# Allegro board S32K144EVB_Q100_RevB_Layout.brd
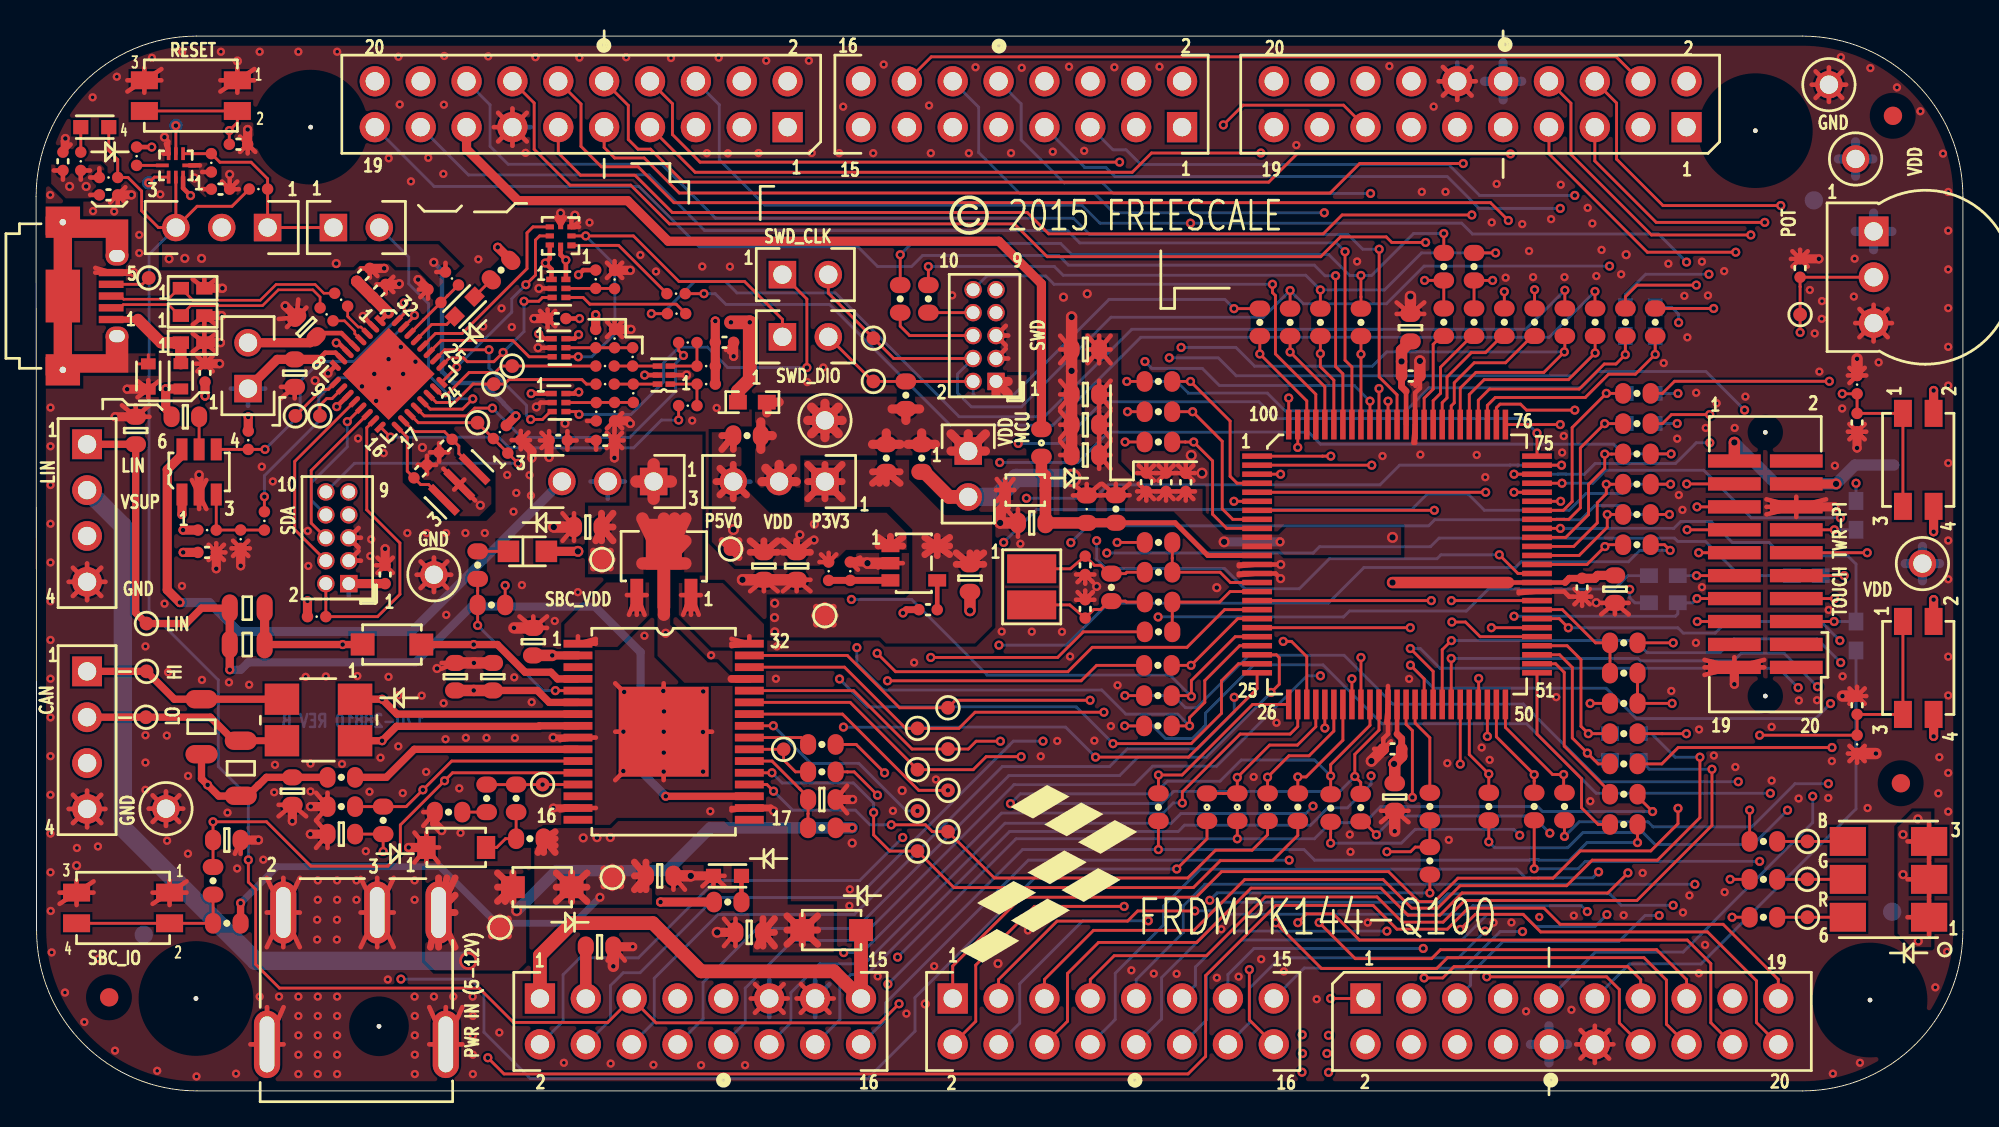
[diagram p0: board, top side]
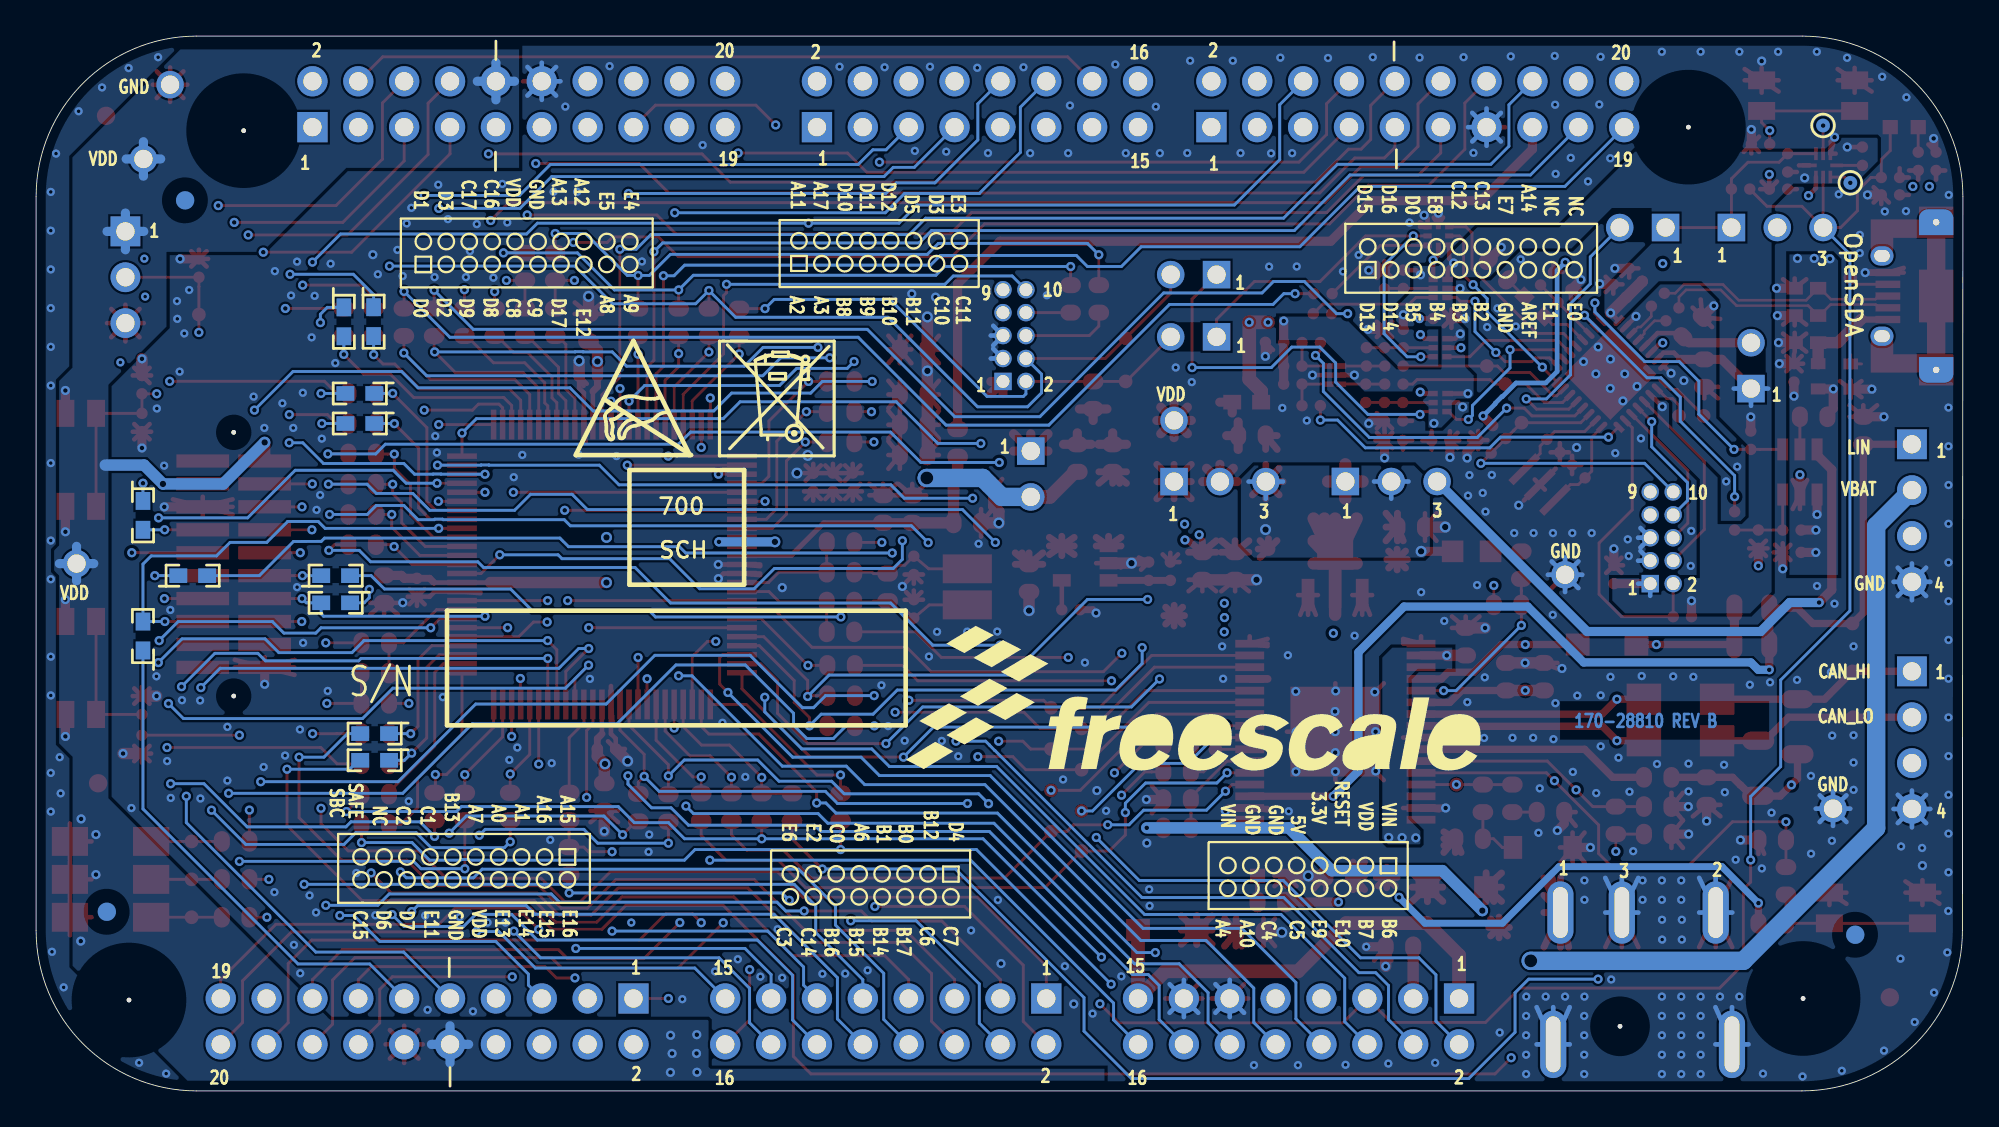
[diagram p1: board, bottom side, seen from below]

Outline 106.71 x 58.42 mm; copper layers: TOP, L2_GND, L3_MIX, BOTTOM. Coordinates in mm from the lower left corner of the outline.
Outline path: 0,49.53 arc(2.6,55.82) 8.89,58.42 97.82,58.42 arc(104.1,55.82) 106.71,49.53 106.71,8.89 arc(104.1,2.6) 97.82,0 8.92,0 arc(2.63,2.6) 0.03,8.89 0.03,8.89 0,49.53

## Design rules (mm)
net group CLOCK: nets SDA_EXTAL SDA_XTAL
net group SDA_USB_CONN_D: nets SDA_USB_CONN_DN SDA_USB_CONN_DP
net group USB_SI_CONN_D: nets SDA_USB_DN SDA_USB_DP
net group POW: nets MIC2005_CSLEW P5V_SDA POWER_EN SDA_RST SDA_USB_P5V_SENSE VREFH VTRG_EN
net group POWER_SPACE: nets P5V0_SDA_USB_CONN_VBUS P5V_SDA_PSW PWR_LED SDA_VOUT33 VCAN VIN
nets with their own width: min track width 0.254; nets GND

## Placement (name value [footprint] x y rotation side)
C1  1000pF  [CC0402_25]  11.21 52.43 0 top
C2  4.7uF  [CC0402_25]  1.49 51.49 90 top
C3  4.7uF  [CC0402_25]  10.21 49.94 0 top
C4  0.1UF  [CC0402_25]  4.01 49.63 0 top
C5  0.1UF  [CC0402_25]  97.69 45.57 90 top
C6  1.0UF  [CC0402_25]  18.12 45.2 45 top
C7  0.1UF  [CC0402_25]  19 44.31 45 top
C8  4.7uF  [CC0402_25]  28.83 42.77 180 top
C9  2.2UF  [CC0603_OV]  14.97 42.31 135 top
C10  0.1UF  [CC0402_25]  38.12 41.46 0 top
C11  10uF  [CC0402_25]  9.35 39.77 90 top
C12  10uF  [CC0603_OV]  14.32 39.75 270 top
C15  18PF  [CC0603_OV]  8.26 37.34 0 top
C16  0.1UF  [CC0402_25]  100.84 37.02 270 top
C17  220PF  [CC0603_OV]  5.51 36.58 90 top
C18  4.7uF  [CC0402_25]  28.92 36.03 180 top
C19  0.1UF  [CC0402_25]  31.52 36.03 0 top
C20  22PF  [CC0402_25]  22.68 35.73 225 top
C21  10uF  [CC0603_OV]  40.3 29.07 270 top
C22  0.1uF  [CC0603_OV]  42.12 29.07 270 top
C23  22PF  [CC0402_25]  21.29 34.31 45 top
C24  10uF  [CC0603_OV]  51.72 28.4 270 top
C25  0.1UF  [CC0402_25]  9.47 29.82 0 top
C26  0.1UF  [CC0402_25]  19.33 28.6 90 top
C27  10uF  [CC0603_OV]  30.55 31.23 180 top
C28  0.1UF  [CC0402_25]  100.85 21.36 90 top
C29  220PF  [CC0603_OV]  27.53 24.88 90 top
C30  2.2UF  [CC0603_OV]  23.22 22.94 90 top
C31  0.1uF  [CC0603_OV]  25.29 22.94 90 top
C40  4700 PF  [CC0603_OV]  14.19 16.6 270 top
C42  0.1uF  [CC0603_OV]  43.52 16.14 0 top
C43  1UF  [CC0603_OV]  58.11 38.57 180 top
C44  82pF  [CC0603_OV]  16.9 14.22 180 top
C46  0.1uF  [CC0603_OV]  10.56 13.89 0 top
C47  0.1uF  [CC0603_OV]  34.53 11.91 0 top
C49  2.2UF  [CC0603_OV]  31.2 7.98 0 top
C59  0.01UF  [CC0402_25]  49.4 26.65 180 top
C126  12PF  [CC0402_25]  58.1 29.11 270 top
C127  12PF  [CC0402_25]  58.1 26.69 90 top
C128  10uF  [CC0603_OV]  39.49 8.78 180 top
C129  1UF  [CC0603_OV]  58.11 35.22 180 top
C131  1UF  [CC0603_OV]  58.11 36.89 180 top
C133  1UF  [CC0603_OV]  76.11 42.27 90 top
C137  1UF  [CC0603_OV]  75.24 16.28 270 top
C140  0.1uF  [CC0402_25]  62.58 33.71 90 top
C141  0.1uF  [CC0402_25]  75.12 18.94 180 top
C142  0.1uF  [CC0402_25]  76.13 39.59 0 top
C143  0.1uF  [CC0402_25]  85.62 27.88 270 top
C144  0.1uF  [CC0402_25]  61.48 33.71 90 top
C145  0.1uF  [CC0402_25]  63.67 33.71 90 top
C146  1UF  [CC0603_OV]  87.43 27.79 270 top
C147  1000PF  [CC0603_OV]  58.11 41.06 180 top
C148  1000PF  [CC0603_OV]  55.14 31.46 180 top
D1  RED  [LED_0603]  3.25 53.38 0 top
D2  LED GREEN  [LED_0603]  23.73 43.44 225 top
D3  GREEN  [LED_0603]  38.29 11.91 180 top
D4  HSMS-C170  [HSMX-C170]  27.21 29.88 180 top
D6  MBR230LSFT1G  [SOD-123]  19.71 24.72 180 top
D7  3.0V  [SOD-323-A]  54.78 33.28 180 top
D8  MMSZ8V2T1G  [SOD123]  23.27 13.48 180 top
D9  MBR230LSFT1G  [SOD-123]  28.03 11.28 0 top
D11  LED RED/GRN/BL  [LED6_5X6MM]  102.58 11.72 180 top
D13  MBR230LSFT1G  [SOD-123]  44.06 8.91 180 top
J1  CON_2X8  [HDR208_ESQ_SKT]  63.46 53.38 270 top
J2  SKT_2x10  [HDR210_ESQ_SKT]  41.62 53.38 270 top
J3  CON_2X8  [HDR208_ESQ_SKT]  27.9 5.12 90 top
J4  CON_2X8  [HDR208_ESQ_SKT]  50.76 5.12 90 top
J5  SKT_2x10  [HDR210_ESQ_SKT]  73.62 5.12 90 top
J6  SKT_2x10  [HDR210_ESQ_SKT]  91.4 53.38 270 top
J7  USB_MICRO_AB  [CON_MICROAB_10F_25_SM_RA]  1.58 44.02 0 top
J8  HDR 1X2 TH  [SH_HDR102_BOTTOM]  41.33 45.21 90 top
J9  HDR 1X2 TH  [SH_HDR102_BOTTOM]  11.73 38.9 180 top
J10  HDR TH 1X3  [HDR103]  43.69 33.75 270 top
J11  HDR 1X4 RA  [CON_HDR_4M_100_TH_RA]  2.82 35.81 270 top
J12  HDR 2X5  [HDR_5X2_FTSH_TH_NSP]  17.32 28.09 180 top
J13  HDR 1X4 RA  [CON_HDR_4M_100_TH_RA]  2.82 23.24 270 top
J14  HDR 2X5  [HDR_5X2_FTSH_TH_NSP]  53.16 39.29 180 top
J15  HDR 1X2 TH  [HDR102]  51.62 35.44 0 top
J16  CON PWR 3  [CON3_PWR_JACK_TH_PJ051A]  22.29 9.88 90 top
J25  CON_2X10  [CON_TFM_20M_50_SM]  95.76 29.17 0 top
J104  HDR_1X3  [HDR103]  12.82 47.82 270 top
J105  HDR 1X2 TH  [SH_HDR102_BOTTOM]  16.46 47.82 90 top
J106  HDR 1X2 TH  [SH_HDR102_BOTTOM]  41.33 41.76 90 top
J107  HDR_1X3  [HDR103]  34.2 33.75 270 top
L1  330 OHM  [IND_1608]  8.02 39.58 270 top
L2  330 OHM  [IND_1608]  6.21 39.57 270 top
L4  B82789C0513N002  [IND_1812_4P]  15.64 20.54 270 top
NOREF  -  []  6.99 51.26 90 top
NOREF#2  -  []  51.49 7.8 0 top
NOREF#3  -  []  -35.57 -162.37 0 top
NOREF#4  -  []  10.97 53.32 90 top
NOREF#5  -  []  18.76 53.38 90 top
NOREF#6  -  [unnamed#2]  102.83 54.01 0 top
NOREF#7  -  []  97.82 0 90 top
NOREF#8  -  []  51.8 48.63 0 top
NOREF#9  -  []  51.17 7.1 0 top
NOREF#10  -  []  102.43 32.55 90 top
NOREF#11  -  []  2.42 11.93 0 top
NOREF#12  -  []  8.89 58.42 0 top
NOREF#13  -  []  103.38 26 0 top
NOREF#14  -  []  53.34 39.01 0 top
NOREF#15  -  []  154.88 58.67 0 top
NOREF#16  -  []  34.41 40.15 0 top
NOREF#17  -  []  98.13 1.31 0 top
NOREF#18  -  []  100.03 8.67 90 top
NOREF#19  -  []  18.76 53.38 0 top
NOREF#20  -  []  7.74 51.91 0 top
NOREF#21  -  []  100.33 9.62 90 top
NOREF#22  -  []  10.09 25.1 0 top
NOREF#23  -  [unnamed#2]  95.21 53.18 0 top
NOREF#24  -  []  68.54 53.38 0 top
NOREF#25  -  []  -67.9 -131.95 0 top
NOREF#26  -  []  -16.59 -34.16 0 top
NOREF#27  -  [unnamed#2]  4.05 5.18 0 top
NOREF#28  -  []  22.19 57.19 90 top
NOREF#29  -  []  17.11 57.19 0 top
NOREF#30  -  [unnamed#2]  15.2 53.38 0 top
NOREF#31  -  []  102.43 37.35 0 top
NOREF#32  -  []  102.43 21.03 90 top
NOREF#33  -  []  88.86 53.38 0 top
NOREF#34  -  []  73.62 5.12 0 top
NOREF#35  -  []  5.99 55.97 0 top
NOREF#36  -  []  95.76 36.47 270 top
NOREF#37  -  []  102.43 25.83 0 top
NOREF#38  -  []  106.71 8.89 90 top
NOREF#39  -  []  -408 -337.34 0 top
NOREF#40  -  [unnamed#2]  103.27 17.04 0 top
NOREF#41  -  []  68.54 53.38 90 top
NOREF#42  -  []  103.38 37.53 0 top
NOREF#43  -  []  39.08 53.38 0 top
NOREF#44  -  []  66.89 57.19 0 top
NOREF#45  -  []  71.97 57.19 90 top
NOREF#46  -  []  100.33 13.82 0 top
NOREF#47  -  [unnamed#2]  101.56 5.03 0 top
NOREF#48  -  []  -381.97 187.81 0 top
NOREF#49  -  []  7.01 51.88 0 top
NOREF#50  -  []  7.94 50.64 90 top
NOREF#51  -  []  8.88 5.05 0 top
NOREF#52  -  []  0 49.53 0 top
NOREF#53  -  []  103.21 1.31 90 top
NOREF#54  -  []  78.85 41.27 0 top
NOREF#55  -  []  6.17 56.92 0 top
NOREF#56  -  []  103.38 20.85 90 top
NOREF#57  -  []  96.48 2.58 90 top
NOREF#58  -  []  103.38 32.38 90 top
NOREF#59  -  [unnamed#2]  8.85 5.12 0 top
NOREF#60  -  []  100.03 14.77 0 top
NOREF#61  -  []  7.22 8.33 90 top
NOREF#62  -  []  2.24 10.98 0 top
NOREF#63  -  []  11.15 54.27 90 top
NOREF#64  -  []  7.39 9.28 90 top
NOREF#65  -  []  73.62 5.12 0 top
NOREF#66  -  []  91.82 42.06 180 bottom
NOREF#67  -  []  39.89 1.44 180 bottom
NOREF#68  -  []  54.61 8.05 180 bottom
NOREF#69  -  []  70.31 54.49 0 bottom
NOREF#70  -  [unnamed#2]  98.45 49.32 180 bottom
NOREF#71  -  []  54.66 15.42 180 bottom
NOREF#72  -  [unnamed#2]  102.79 9.92 180 bottom
NOREF#73  -  []  171.98 13.39 270 bottom
NOREF#74  -  [unnamed#2]  5.96 8.65 180 bottom
NOREF#75  -  []  65.81 40.19 180 bottom
NOREF#76  -  []  38.46 17.65 180 bottom
Q1  BCX53  [SOT89_31]  34.76 29.61 0 top
R1  4.7K  [RC0402_25]  5.57 51.77 90 top
R2  330 OHM  [RC0402_25]  2.47 51.49 270 top
R3  10.0K  [RC0402_25]  9.7 51.4 90 top
R4  180K  [RC0402_25]  4.01 50.59 0 top
R5  0  [RC0402_25]  12.31 49.95 180 top
R12  220  [RC0603_OV]  25.75 45.46 225 top
R13  5K  [POT3_3352T]  101.76 47.6 270 top
R14  4.7K  [RC0402_25]  23.03 45 315 top
R15  4.7K  [RC0402_25]  30.99 44.95 270 top
R16  10.0K  [RC0402_25]  32.03 44.94 90 top
R18  0  [RC0402_25]  35.44 44.16 0 top
R20  10.0K  [RC0402_25]  22.06 44.03 135 top
R21  33  [RC0402_25]  16.89 43.82 315 top
R24  0  [RC0402_25]  35.47 43.05 180 top
R25  33  [RC0402_25]  16.09 43.01 315 top
R30  4.7K  [RC0402_25]  30.99 41.67 270 top
R31  10.0K  [RC0402_25]  32.03 41.67 90 top
R32  0  [RC0402_25]  36.09 41.45 180 top
R35  0  [RC0402_25]  33.04 40.65 90 top
R38  0  [RC0402_25]  31.51 40.15 180 top
R39  10.0K  [RC0402_25]  37.11 40.15 0 top
R41  0  [RC0402_25]  31.51 39.15 180 top
R42  10.0K  [RC0402_25]  37.11 39.15 180 top
R44  10.0K  [RC0402_25]  100.85 39.12 90 top
R47  0  [RC0402_25]  33.07 38.64 270 top
R49  0  [RC0402_25]  36.09 37.95 180 top
R51  10.0K  [RC0402_25]  32.03 37.62 270 top
R52  4.7K  [RC0402_25]  31.02 37.61 90 top
R56  330  [RC0603_OV]  38.3 10.46 180 top
R57  4.7K  [RC0402_25]  25.68 36.49 225 top
R60  10.0K  [RC0402_25]  11.75 36.04 270 top
R62  10.0K  [RC0402_25]  26.48 35.68 45 top
R63  0  [RC0603_OV]  47.08 35.05 90 top
R64  0  [RC0603_OV]  39.37 36.29 0 top
R68  15K  [RC0402_25]  11.33 30.56 270 top
R69  1.0K  [RC0402_25]  12.64 31.57 270 top
R70  10.0K  [RC0402_25]  9.47 31.06 0 top
R73  1K  [RC0603_OV]  24.46 29.12 270 top
R74  10.0K  [RC0402_25]  100.85 19.19 270 top
R75  0  [RC0603_OV]  25.21 26.92 180 top
R77  10.0K  [RC0402_25]  15.54 26.27 0 top
R80  2K  [RC0805_OV]  11.69 24.72 0 top
R81  0  [RC0603_OV]  62.16 25.42 0 top
R84  0  [RC0603_OV]  62.16 27.08 180 top
R88  0  [RC0603_OV]  62.16 28.73 180 top
R90  0  [RC0603_OV]  62.16 30.38 0 top
R91  1.0M  [RC0603_OV]  59.55 27.89 270 top
R92  60.4  [RC1206_OV]  9.16 20.17 270 top
R93  0  [RC0603_OV]  43.52 19.19 180 top
R95  220  [RC0603_OV]  95.66 13.82 180 top
R96  220  [RC0603_OV]  95.66 11.72 180 top
R97  220  [RC0603_OV]  95.66 9.62 180 top
R98  60.4  [RC1206_OV]  11.34 17.87 270 top
R99  1K  [RC0603_OV]  59.8 32.23 270 top
R100  0  [RC0603_OV]  16.9 17.37 0 top
R102  0  [RC0603_OV]  43.52 17.67 180 top
R103  0  [RC0603_OV]  58.18 32.22 270 top
R104  0  [RC0603_OV]  24.95 16.2 90 top
R105  0  [RC0603_OV]  26.58 16.2 90 top
R107  4.7K  [RC0603_OV]  16.9 15.75 180 top
R108  4.7K  [RC0603_OV]  22.84 15.44 180 top
R109  0  [RC0603_OV]  55.67 35.89 90 top
R110  1K  [RC0603_OV]  43.52 14.57 180 top
R112  120.0  [RC0603_OV]  19.22 14.98 270 top
R113  4.7K  [RC0603_OV]  27.35 13.97 180 top
R116  12.0K  [RC0603_OV]  9.8 11.64 90 top
R117  0  [RC0603_OV]  49.04 35.05 270 top
R118  12.0K  [RC0603_OV]  10.56 9.28 180 top
R119  0  [RC0603_OV]  47.85 43.87 90 top
R120  0  [RC0603_OV]  49.41 43.87 90 top
R121  10K  [RC0603_OV]  48.17 38.53 90 top
R122  0  [RC0603_OV]  67.77 42.57 90 top
R123  0  [RC0603_OV]  73.37 42.56 90 top
R124  0  [RC0603_OV]  88.65 35.28 0 top
R125  0  [RC0603_OV]  88.65 33.6 0 top
R126  0  [RC0603_OV]  88.65 31.93 0 top
R127  0  [RC0603_OV]  69.45 42.56 90 top
R128  0  [RC0603_OV]  71.12 42.57 90 top
R129  0  [RC0603_OV]  88.65 30.25 180 top
R130  0  [RC0603_OV]  69.87 15.71 90 top
R131  0  [RC0603_OV]  68.2 15.71 90 top
R132  0  [RC0603_OV]  66.52 15.71 90 top
R133  0  [RC0603_OV]  87.92 16.43 180 top
R134  0  [RC0603_OV]  87.92 14.76 180 top
R135  0  [RC0603_OV]  62.15 15.71 90 top
R136  0  [RC0603_OV]  62.15 37.62 0 top
R137  0  [RC0603_OV]  62.15 35.94 0 top
R140  0  [RC0603_OV]  79.63 45.65 270 top
R141  0  [RC0603_OV]  77.96 45.65 270 top
R142  0  [RC0603_OV]  77.18 12.74 90 top
R143  0  [RC0603_OV]  87.92 21.46 0 top
R144  0  [RC0603_OV]  79.63 42.57 270 top
R145  0  [RC0603_OV]  77.96 42.57 270 top
R146  0  [RC0603_OV]  77.18 15.75 90 top
R147  0  [RC0603_OV]  87.92 23.14 180 top
R152  0  [RC0603_OV]  84.64 15.75 270 top
R153  0  [RC0603_OV]  82.96 15.75 270 top
R154  0  [RC0603_OV]  62.12 20.22 180 top
R155  0  [RC0603_OV]  62.12 21.89 180 top
R156  0  [RC0603_OV]  62.15 39.29 180 top
R159  0  [RC0603_OV]  62.12 23.57 0 top
R161  0  [RC0603_OV]  84.66 42.57 90 top
R162  0  [RC0603_OV]  86.34 42.57 90 top
R163  0  [RC0603_OV]  64.84 15.71 270 top
R164  0  [RC0603_OV]  80.45 15.75 270 top
R165  0  [RC0603_OV]  82.99 42.57 90 top
R166  0  [RC0603_OV]  73.36 15.69 270 top
R167  0  [RC0603_OV]  81.31 42.57 90 top
R168  0  [RC0603_OV]  71.69 15.67 270 top
R169  0  [RC0402_25]  43.89 28.78 270 top
R170  0  [RC0402_25]  45.09 28.78 270 top
R171  2K  [RC0805_OV]  11.69 26.74 0 top
R172  0  [RC0603_OV]  88.02 42.57 270 top
R173  0  [RC0603_OV]  89.67 42.57 270 top
R174  0  [RC0603_OV]  87.92 24.82 180 top
R175  0  [RC0603_OV]  87.92 19.79 180 top
R176  0  [RC0603_OV]  87.92 18.11 180 top
R179  0  [RC0603_OV]  88.65 38.63 180 top
R180  0  [RC0603_OV]  88.65 36.96 180 top
SH1  0  [SH0603]  39.66 38.15 0 top
SH4  0  [SH0603]  87.96 18.31 0 bottom
SH5  0  [SH0603]  87.96 19.79 0 bottom
SH8  0  [SH0603]  100.79 31.88 270 bottom
SH9  0  [SH0603]  88.02 42.61 270 bottom
SH10  0  [SH0603]  89.66 42.6 270 bottom
SH11  0  [SH0603]  90.12 28.54 180 bottom
SH12  0  [SH0603]  98.03 28.54 180 bottom
SH13  0  [SH0603]  90.12 27.03 0 bottom
SH14  0  [SH0603]  88.78 38.63 0 bottom
SH15  0  [SH0603]  88.78 36.96 0 bottom
SH16  0  [SH0603]  100.79 25.19 90 bottom
SW2  EVQ-P2402W  [SW4_SPST_4P8X3P6_2P5]  104.23 34.95 90 top
SW3  EVQ-P2402W  [SW4_SPST_4P8X3P6_2P5]  104.23 23.43 90 top
SW5  EVQ-P2402W  [SW4_SPST_4P8X3P6_2P5]  8.57 55.12 0 top
SW6  EVQ-P2402W  [SW4_SPST_4P8X3P6_2P5]  4.82 10.13 0 top
TP1  TEST POINT BLACK  [TEST_LOOP]  99.29 55.73 270 top
TP4  TEST POINT BLACK  [TEST_LOOP]  100.76 51.62 270 top
TP5  -  [TPAD_030]  97.69 43 270 top
TP6  -  [TPAD_030]  6.24 45.03 90 top
TP7  -  [TPAD_030]  26.37 40.15 315 top
TP8  -  [TPAD_030]  25.35 39.15 315 top
TP9  TEST POINT BLACK  [TEST_LOOP]  43.69 37.13 270 top
TP10  -  [TPAD_030]  14.36 37.39 90 top
TP11  -  [TPAD_030]  15.72 37.39 90 top
TP12  -  [TPAD_030]  24.44 37.01 90 top
TP13  -  [TPAD_030]  43.68 26.32 90 top
TP14  -  [TPAD_030]  38.46 30.01 225 top
TP15  -  [TPAD_030]  31.33 29.43 270 top
TP16  TEST POINT BLACK  [TEST_LOOP]  104.47 29.2 270 top
TP17  TEST POINT BLACK  [TEST_LOOP]  22.03 28.59 270 top
TP18  -  [TPAD_030]  6.11 25.89 90 top
TP19  -  [TPAD_030]  6.11 23.24 180 top
TP20  -  [TPAD_030]  50.5 21.22 90 top
TP21  -  [TPAD_030]  48.81 20.08 90 top
TP22  -  [TPAD_030]  6.08 20.7 180 top
TP23  -  [TPAD_030]  50.5 18.93 0 top
TP24  -  [TPAD_030]  41.4 18.92 0 top
TP25  -  [TPAD_030]  48.81 17.79 0 top
TP26  -  [TPAD_030]  28.05 16.97 270 top
TP27  -  [TPAD_030]  50.5 16.65 180 top
TP28  -  [TPAD_030]  98.09 13.82 180 top
TP29  -  [TPAD_030]  98.09 11.72 270 top
TP30  -  [TPAD_030]  98.09 9.62 0 top
TP31  -  [TPAD_030]  46.37 41.69 180 top
TP32  TEST POINT BLACK  [TEST_LOOP]  7.19 15.63 270 top
TP33  -  [TPAD_030]  48.81 15.5 180 top
TP34  -  [TPAD_030]  46.37 39.29 180 top
TP35  -  [TPAD_030]  48.81 13.28 0 top
TP36  -  [TPAD_030]  31.91 11.82 0 top
TP37  -  [TPAD_030]  50.5 14.36 0 top
TP38  -  [TPAD_030]  25.69 9.05 0 top
TP500  -  [TPAD_030]  7.74 53.47 90 bottom
TP501  -  [TPAD_030]  6.23 50.29 90 bottom
U1  NTSX2102GU8H  [XQFN8_1P45X1P25MM]  7.74 51.26 180 top
U2  74LVC2T45GM,125  [QFN8_1P6X1P6MM]  29.05 47.35 180 top
U3  0402ESDA-MLP  [0402_MLP]  8.67 44.46 0 top
U4  74LVCH1T45  [UDFN6_1X1P5MM]  28.96 44.44 0 top
U5  0402ESDA-MLP  [0402_MLP]  8.67 42.94 0 top
U6  0402ESDA-MLP  [0402_MLP]  8.67 41.44 0 top
U7  74LVCH1T45  [UDFN6_1X1P5MM]  28.96 41.16 0 top
U8  MK20DX128VFM5  [QFN32_S142EP]  19.52 39.71 315 top
U9  NLX2G14  [UDFN6_1P45X1_0P5MM]  34.77 39.65 180 top
U10  74LVCH1T45  [UDFN6_1X1P5MM]  28.96 38.12 0 top
U11  MIC2005-0.8YM6  [SOT23-6_A]  9.03 34.28 90 top
U15  SPX3819M5-L-3-3  [SOT23_5S]  48.61 29.23 270 top
U17  PS32K144HFT0VLLT  [LQFP100_0P5_14X14]  75.37 29.16 0 top
U19  MCZ33903CS5EK  [SOIC32_0P65_7P6X11P1]  34.75 19.89 0 top
Y1  8.00MHZ  [XTAL3_3P35X1P45_SM]  23.43 33.58 45 top
Y3  8MHZ  [XTAL2_3P3X2P6]  55.14 27.92 270 top

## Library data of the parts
C1 C6 C9 C11 C16 C17 C20-C24 C27-C31 C40 C42-C44 C46 C47 C49 C126-C129 C131 C133 C137 C140-C148 = CAP_NP
C2-C5 C7 C8 C10 C12 C18 C19 C25 C26 = CAP_NP: tolerance: 10%
C15 = CAP_NP: tolerance: 5%
C59 = CAP_NP: tolerance: 20%
D1-D4 = LED
D6 D9 D13 = DIODE_SCHTKY
D7 D8 = ZDIODE
D11 = LED_TRI_COLOR
J1 J3 J4 = CONN_HDR_8X2
J2 J5 J6 = CONN_HDR_10X2
J7 = MICRO_USB_CONN_10PIN
J8 J9 J105 J106 = CONN_HDR_2X1
J10 J104 J107 = CONN_HDR_3X1
J11 J13 = CONN_HDR_4X1
J12 J14 = CONN_HDR_5X2
J15 = JUMPER_2_2mm
J16 = DC_POWER_JACK_SHD
J25 = CONN_SHRHDR_10X2
L1 L2 = BEAD
L4 = DATA_CHOKE
Q1 = PNP_BCX53
R1 R14 R15 R30 R44 R52 R57 R60 R68-R70 R74 = RES: tolerance: 1%
R2 R4 R12 R20 R21 R25 R32 R35 R38 R41 R47 R49 R56 R62-R64 R73 R75 R77 R80 R81 R84 R88 R90-R93 R95-R100 R102-R105 R107-R110 R112 R113 R116-R137 R140-R147 R152-R156 R159 R161-R176 R179 R180 = RES
R3 R5 R16 R18 R24 R31 R39 R42 R51 = RES: tolerance: 5%
R13 = POT: tolerance: 20%
SH1 SH4 SH5 SH8-SH16 = RES_SHORT-2
SW2 SW3 SW5 SW6 = EDGE_MOUNT_PB_SW_2
TP1 TP4-TP38 TP500 TP501 = TestLoop
U1 = NTSX2102GU8H_8P
U2 = 74LVC2T45GM_8P
U3 U5 U6 = DIODE_TVS_BIDIR
U4 U7 U10 = 74LVCH1T45_6P
U8 = PK20DX128V_QFN_32P
U9 = NLX2G14_6P
U11 = MIC2005-0.8YM6
U15 = SPX3819M5_FIX_5P
U17 = PS32K144_LQFP_100P
U19 = MCZ33903S_SOIC_32P
Y1 = XTAL_CS
Y3 = XTAL_CS10

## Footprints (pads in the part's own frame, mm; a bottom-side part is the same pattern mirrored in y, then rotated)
0402_MLP
  rect 0.9x0.7 smd: 1(-0.65,0) 2(0.65,0)
CC0402_25
  round 0.635 smd: 1(-0.508,0) 2(0.508,0)
CC0603_OV
  oval 0.889x1.143 smd: 1(-0.762,0) 2(0.762,0)
CON3_PWR_JACK_TH_PJ051A
  round 0.254 hole 2.54 unplated: (-6.3,3.3)
  oval 3.454x1.448 hole 2.819x0.813: 1(0,0) 2(0,8.6) 3(0,3.4)
  oval 3.734x1.448 hole 3.099x0.813: SH1(-7.3,9.5) SH2(-7.3,-0.4)
CON_HDR_4M_100_TH_RA
  rect 1.651x1.651 hole 1.016: 1(0,0)
  round 1.651 hole 1.016: 2(2.54,0) 3(5.08,0) 4(7.62,0)
CON_MICROAB_10F_25_SM_RA
  rect 1.372x0.406 smd: 1(2.575,-1.3) 2(2.575,-0.65) 3(2.575,0) 4(2.575,0.65) 5(2.575,1.3)
  oval 1.27x1.067 hole 0.864x0.66: 6(2.9,2.225) 7(2.9,-2.225)
  rect 1.905x2.921 smd: 8(-0.1,0)
  custom 0.356x0.356 hole 1.524x0.838: 9(-0.1,4.09) 10(-0.1,-4.09)
CON_TFM_20M_50_SM
  round 0.254 hole 1.346 unplated: (0,7.303) (0,-7.303)
  rect 2.921x0.737 smd: 1(-1.714,5.715) 2(1.714,5.715) 3(-1.714,4.445) 4(1.714,4.445) 5(-1.714,3.175) 6(1.714,3.175) 7(-1.714,1.905) 8(1.714,1.905) 9(-1.714,0.635) 10(1.714,0.635) 11(-1.714,-0.635) 12(1.714,-0.635) 13(-1.714,-1.905) 14(1.714,-1.905) 15(-1.714,-3.175) 16(1.714,-3.175) 17(-1.714,-4.445) 18(1.714,-4.445) 19(-1.714,-5.715) 20(1.714,-5.715)
HDR102
  rect 1.524x1.524 hole 1.016: 1(0,0)
  round 1.524 hole 1.016: 2(0,-2.54)
HDR103
  rect 1.524x1.524 hole 1.016: 1(0,0)
  round 1.524 hole 1.016: 2(0,-2.54) 3(0,-5.08)
HDR208_ESQ_SKT
  rect 1.676x1.676 hole 1.016: 1(0,0)
  round 1.676 hole 1.016: 2(-2.54,0) 3(0,-2.54) 4(-2.54,-2.54) 5(0,-5.08) 6(-2.54,-5.08) 7(0,-7.62) 8(-2.54,-7.62) 9(0,-10.16) 10(-2.54,-10.16) 11(0,-12.7) 12(-2.54,-12.7) 13(0,-15.24) 14(-2.54,-15.24) 15(0,-17.78) 16(-2.54,-17.78)
HDR210_ESQ_SKT
  rect 1.676x1.676 hole 1.016: 1(0,0)
  round 1.676 hole 1.016: 2(-2.54,0) 3(0,-2.54) 4(-2.54,-2.54) 5(0,-5.08) 6(-2.54,-5.08) 7(0,-7.62) 8(-2.54,-7.62) 9(0,-10.16) 10(-2.54,-10.16) 11(0,-12.7) 12(-2.54,-12.7) 13(0,-15.24) 14(-2.54,-15.24) 15(0,-17.78) 16(-2.54,-17.78) 17(0,-20.32) 18(-2.54,-20.32) 19(0,-22.86) 20(-2.54,-22.86)
HDR_5X2_FTSH_TH_NSP
  rect 0.965x0.965 hole 0.711: 1(0,0)
  round 0.965 hole 0.711: 2(1.27,0) 3(0,-1.27) 4(1.27,-1.27) 5(0,-2.54) 6(1.27,-2.54) 7(0,-3.81) 8(1.27,-3.81) 9(0,-5.08) 10(1.27,-5.08)
HSMX-C170
  rect 1.194x1.194 smd: A(-1.05,0) C(1.05,0)
IND_1608
  rect 0.61x0.813 smd: 1(-0.7,0) 2(0.7,0)
IND_1812_4P
  rect 1.73x1.91 smd: 1(-1.15,2.025) 2(-1.15,-2.025) 3(1.15,2.025) 4(1.15,-2.025)
LED6_5X6MM
  rect 2.007x1.6 smd: A1(-2.25,2.1) A2(-2.25,0) A3(-2.25,-2.1) C1(2.25,2.1) C2(2.25,0) C3(2.25,-2.1)
LED_0603
  rect 0.838x0.787 smd: A(-0.775,0) C(0.775,0)
LQFP100_0P5_14X14
  rect 1.651x0.305 smd: 1(-7.75,6) 2(-7.75,5.5) 3(-7.75,5) 4(-7.75,4.5) 5(-7.75,4) 6(-7.75,3.5) 7(-7.75,3) 8(-7.75,2.5) 9(-7.75,2) 10(-7.75,1.5) 11(-7.75,1) 12(-7.75,0.5) 13(-7.75,0) 14(-7.75,-0.5) 15(-7.75,-1) 16(-7.75,-1.5) 17(-7.75,-2) 18(-7.75,-2.5) 19(-7.75,-3) 20(-7.75,-3.5) 21(-7.75,-4) 22(-7.75,-4.5) 23(-7.75,-5) 24(-7.75,-5.5) 25(-7.75,-6) 51(7.75,-6) 52(7.75,-5.5) 53(7.75,-5) 54(7.75,-4.5) 55(7.75,-4) 56(7.75,-3.5) 57(7.75,-3) 58(7.75,-2.5) 59(7.75,-2) 60(7.75,-1.5) 61(7.75,-1) 62(7.75,-0.5) 63(7.75,0) 64(7.75,0.5) 65(7.75,1) 66(7.75,1.5) 67(7.75,2) 68(7.75,2.5) 69(7.75,3) 70(7.75,3.5) 71(7.75,4) 72(7.75,4.5) 73(7.75,5) 74(7.75,5.5) 75(7.75,6)
  rect 0.305x1.651 smd: 26(-6,-7.75) 27(-5.5,-7.75) 28(-5,-7.75) 29(-4.5,-7.75) 30(-4,-7.75) 31(-3.5,-7.75) 32(-3,-7.75) 33(-2.5,-7.75) 34(-2,-7.75) 35(-1.5,-7.75) 36(-1,-7.75) 37(-0.5,-7.75) 38(0,-7.75) 39(0.5,-7.75) 40(1,-7.75) 41(1.5,-7.75) 42(2,-7.75) 43(2.5,-7.75) 44(3,-7.75) 45(3.5,-7.75) 46(4,-7.75) 47(4.5,-7.75) 48(5,-7.75) 49(5.5,-7.75) 50(6,-7.75) 76(6,7.75) 77(5.5,7.75) 78(5,7.75) 79(4.5,7.75) 80(4,7.75) 81(3.5,7.75) 82(3,7.75) 83(2.5,7.75) 84(2,7.75) 85(1.5,7.75) 86(1,7.75) 87(0.5,7.75) 88(0,7.75) 89(-0.5,7.75) 90(-1,7.75) 91(-1.5,7.75) 92(-2,7.75) 93(-2.5,7.75) 94(-3,7.75) 95(-3.5,7.75) 96(-4,7.75) 97(-4.5,7.75) 98(-5,7.75) 99(-5.5,7.75) 100(-6,7.75)
POT3_3352T
  rect 1.651x1.651 hole 1.016: 1(0,0)
  round 1.651 hole 1.016: 2(2.54,0) 3(5.08,0)
QFN8_1P6X1P6MM
  rect 0.457x0.33 smd: 1(-0.6,0.525)
  rect 0.457x0.279 smd: 2(-0.6,0) 3(-0.6,-0.5) 5(0.6,-0.5) 6(0.6,0) 7(0.6,0.5)
  rect 0.279x0.457 smd: 4(0,-0.6) 8(0,0.6)
QFN32_S142EP
  custom 0.07x0.07 smd: 1(-2.4,1.751) 2(-2.4,1.251) 3(-2.4,0.751) 4(-2.4,0.25) 5(-2.4,-0.25) 6(-2.4,-0.751) 7(-2.4,-1.251) 8(-2.4,-1.751) 9(-1.751,-2.4) 10(-1.251,-2.4) 11(-0.751,-2.4) 12(-0.25,-2.4) 13(0.25,-2.4) 14(0.751,-2.4) 15(1.251,-2.4) 16(1.751,-2.4) 17(2.4,-1.751) 18(2.4,-1.251) 19(2.4,-0.751) 20(2.4,-0.25) 21(2.4,0.25) 22(2.4,0.751) 23(2.4,1.251) 24(2.4,1.751) 25(1.751,2.4) 26(1.251,2.4) 27(0.751,2.4) 28(0.25,2.4) 29(-0.25,2.4) 30(-0.751,2.4) 31(-1.251,2.4) 32(-1.751,2.4)
  rect 3.607x3.607 smd: 33(0,0)
RC0402_25
  round 0.635 smd: 1(-0.508,0) 2(0.508,0)
RC0603_OV
  oval 0.889x1.143 smd: 1(-0.762,0) 2(0.762,0)
RC0805_OV
  oval 0.889x1.524 smd: 1(-0.965,0) 2(0.965,0)
RC1206_OV
  oval 1.016x1.778 smd: 1(-1.524,0) 2(1.524,0)
SH0603
  rect 0.991x0.813 smd: 1(-0.8,0) 2(0.8,0)
SH_HDR102_BOTTOM
  rect 1.524x1.524 hole 1.016: 1(0,0)
  round 1.524 hole 1.016: 2(0,-2.54)
SOD123
  rect 1.016x1.27 smd: A(1.651,0) C(-1.651,0)
SOD-123
  rect 1.321x1.219 smd: A(-1.626,0) C(1.626,0)
SOD-323-A
  rect 0.635x0.838 smd: A(1.115,0) C(-1.115,0)
SOIC32_0P65_7P6X11P1
  rect 1.6x0.432 smd: 1(-4.745,4.875) 2(-4.745,4.225) 3(-4.745,3.575) 4(-4.745,2.925) 5(-4.745,2.275) 6(-4.745,1.625) 7(-4.745,0.975) 8(-4.745,0.325) 9(-4.745,-0.325) 10(-4.745,-0.975) 11(-4.745,-1.625) 12(-4.745,-2.275) 13(-4.745,-2.925) 14(-4.745,-3.575) 15(-4.745,-4.225) 16(-4.745,-4.875) 17(4.745,-4.875) 18(4.745,-4.225) 19(4.745,-3.575) 20(4.745,-2.925) 21(4.745,-2.275) 22(4.745,-1.625) 23(4.745,-0.975) 24(4.745,-0.325) 25(4.745,0.325) 26(4.745,0.975) 27(4.745,1.625) 28(4.745,2.275) 29(4.745,2.925) 30(4.745,3.575) 31(4.745,4.225) 32(4.745,4.875)
  rect 4.978x4.978 smd: 33(0,0)
SOT23-6_A
  rect 1.219x0.61 smd: 1(-1.25,0.95) 2(-1.25,0) 3(-1.25,-0.95) 4(1.25,-0.95) 5(1.25,0) 6(1.25,0.95)
SOT23_5S
  rect 0.686x0.991 smd: 1(-0.953,-1.295) 2(0,-1.295) 3(0.953,-1.295) 4(0.953,1.295) 5(-0.953,1.295)
SOT89_31
  rect 0.711x1.803 smd: 1(1.5,-2.15) 3(-1.5,-2.15)
  custom 0.5x0.5 smd: 2(0,-0.4)
SW4_SPST_4P8X3P6_2P5
  rect 1.499x0.991 smd: 1(2.575,0.85) 2(2.575,-0.85) 3(-2.575,0.85) 4(-2.575,-0.85)
TEST_LOOP
  round 1.524 hole 1.016: 1(0,0)
TPAD_030
  round 0.762 smd: 1(0,0)
UDFN6_1P45X1_0P5MM
  rect 0.533x0.305 smd: 1(-0.354,0.5) 2(-0.354,0) 3(-0.354,-0.5) 4(0.354,-0.5) 5(0.354,0) 6(0.354,0.5)
UDFN6_1X1P5MM
  rect 0.584x0.305 smd: 1(-0.418,0.5)
  rect 0.508x0.305 smd: 2(-0.38,0) 3(-0.38,-0.5) 4(0.38,-0.5) 5(0.38,0) 6(0.38,0.5)
unnamed#2
  round 1.016 smd: (0,0)
XQFN8_1P45X1P25MM
  rect 0.787x0.203 smd: 1(-0.75,0)
  rect 0.203x0.711 smd: 2(-0.4,-0.65) 3(0,-0.65) 4(0.4,-0.65) 6(0.4,0.65) 7(0,0.65) 8(-0.4,0.65)
  rect 0.711x0.203 smd: 5(0.75,0)
XTAL2_3P3X2P6
  rect 1.6x2.718 smd: 1(-1,0) 2(1,0)
XTAL3_3P35X1P45_SM
  rect 0.406x2.108 smd: 1(1.2,0) 2(0,0) 3(-1.2,0)

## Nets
GND: C1.2 C2.2 C3.2 C4.2 C5.2 C6.2 C7.2 C8.2 C9.2 C10.2 C11.2 C12.2 C16.2 C17.2 C18.2 C19.2 C20.2 C21.2 C22.2 C23.2 C24.2 C25.2 C26.2 C27.2 C28.2 C29.2 C30.2 C31.2 C40.2 C42.2 C43.2 C44.2 C46.2 C47.2 C49.2 C59.2 C126.2 C127.2 C128.2 C129.2 C131.2 C133.2 C137.2 C140.2 C141.2 C142.2 C143.2 C144.2 C145.2 C146.2 C147.2 C148.2 D3.C(CATHODE) D7.A(ANODE) D8.A(ANODE) J2.13 J3.11(A6) J3.13(A7) J5.12 J6.12 J7.5(GND) J11.4 J12.3(A2) J12.5(A3) J13.4 J14.3(A2) J14.5(A3) J16.2 J16.3 J16.SH1(SHIELD1) J16.SH2(SHIELD2) J25.6(B3) J25.19(A10) L2.2 R13.3(B) R16.2 R20.2 R31.2 R44.2 R51.2 R62.2 R68.2 R74.2 R107.2 R108.2 R170.1 SW5.1 SW5.3 SW6.1 SW6.3 TP1.1(PIN1) TP17.1(PIN1) TP32.1(PIN1) U1.4(GND) U2.3(DIR) U2.4(GND) U3.2(A2) U4.2(GND) U5.2(A2) U6.2(A2) U7.2(GND) U8.2(VSS1) U8.8(VSSA) U8.33(EPAD) U9.2(GND) U10.2(GND) U11.2(GND) U15.2(GND) U17.13(VREFL) U17.14(VSS1) U17.37(VSS2) U17.60(VSS3) U17.86(VSS4) U19.9(GND-CAN) U19.15(GND1) U19.18(GND2) U19.33(EXPAD) Y1.2
P3V3: C24.1 J3.7(A4) J10.1 R63.1 TP13.1(PIN1) U15.5(VOUT)
P3V3_SDA: C3.1 C6.1 C7.1 C10.1 C12.1 C18.1 C19.1 C26.1 J9.1 J12.1(A1) R1.2 R3.1 R12.1 R15.1 R30.1 R39.2 R42.1 R52.1 R60.1 R77.1 U1.1(VCCA) U2.7(VCCA) U4.1(VCCA) U7.1(VCCA) U8.1(VDD1) U8.7(VDDA) U8.11(VBAT) U9.5(VCC) U10.1(VCCA)
P5V0: C21.1 C22.1 D4.A(ANODE) J3.9(A5) J10.3 J107.2 R64.1 R169.1 TP14.1(PIN1) U15.1(VIN)
P5V0_SDA_USB_CONN_VBUS: J7.1(VBUS) L1.1 U6.1(A1)
P5V_SDA: C11.1 C15.1 C25.1 L1.2 R14.1 R57.1 R70.1 U8.6(VREGIN) U11.1(VIN)
P5V_SDA_PSW: J107.3 U11.6(VOUT)
VBATT: D9.A J11.2 J16.1 R110.1 TP38.1(PIN1)
VDD: C49.1 D11.A1(ANODE1) D11.A2(ANODE2) D11.A3(ANODE3) J3.3(A2) J5.10 J6.10 J10.2 J14.1(A1) J15.1 J25.1(A1) J25.4(B2) R13.1(A) R56.2 R63.2 R64.2 R117.1 R121.1 SH1.2 SW2.2 SW2.4 SW3.2 SW3.4 TP4.1(PIN1) TP9.1(PIN1) TP16.1(PIN1)
VDD_MCU: C43.1 C129.1 C131.1 C133.1 C137.1 C140.1 C141.1 C142.1 C143.1 C144.1 C145.1 C146.1 C147.1 J15.2 R99.1 R103.1 R117.2 U17.10(VDD1) U17.11(VDDA) U17.38(VDD2) U17.61(VDD3) U17.87(VDD4)
VIN: D13.A J3.1(A1) J3.15(A8)
ADC0_SE12: C5.1 R13.2(WIPER) R164.2 TP5.1(PIN1)
AREF: J2.15 R109.2
BTN0: C16.1 R44.1 R152.2 SW2.1 SW2.3
BTN1: C28.1 R74.1 R153.2 SW3.1 SW3.3
CAN_HI: J13.1 L4.2(IN2) R92.1 TP19.1(PIN1)
CAN_LO: J13.2 L4.4(OUT2) R98.1 TP22.1(PIN1)
ELEC_IN0: J25.3(A2) R172.1
ELEC_IN1: J25.5(A3) R173.1
ELEC_IN2: J25.7(A4) R174.1
ELEC_IN4: J25.9(A5) R175.1
ELEC_IN5: J25.10(B5) R176.1
ELEC_IN9: J25.14(B7) R179.1
ELEC_IN10: J25.15(A8) R180.1
JTAG_TCLK/SWD_CLK: J8.2 J14.4(B2) R127.2 R143.1 TP31.1(PIN1)
JTAG_TDI: R120.2 R128.2 R140.1
JTAG_TDO: R119.2 R123.2 R141.1
JTAG_TMS/SWD_DIO_PTA4: J14.2(B1) J106.2 R121.2 R122.2 R142.1 TP34.1(PIN1)
LEDRGB_BLUE: D11.C3(CATHODE3) R95.1 TP28.1(PIN1)
LEDRGB_GREEN: D11.C2(CATHODE2) R96.1 TP29.1(PIN1)
LEDRGB_RED: D11.C1(CATHODE1) R97.1 TP30.1(PIN1)
LIN: C17.1 J11.1 R80.1 R171.1 TP18.1(PIN1) U19.19(LIN)
LIN_MASTER: D6.C R80.2 R171.2
LVLRST_EN: R1.1 U1.5(OE)
MIC2005_CSLEW: C15.2 U11.5(CSLEW)
POWER_EN: R69.1 U8.31(ADC0_SE7B/PTD6/SPI0_PCS3/UART0_)
PTA0: R172.2 SH9.2 U17.79(PTA0/ADC0_SE0/ACMP0_IN0/FTM2_CH)
PTA1: R173.2 SH10.2 U17.78(PTA1/ADC0_SE1/ACMP0_IN1/FTM1_CH)
PTA2: J25.11(A6) SH11.1 U17.73(PTA2/ADC1_SE0/FTM3_CH0/LPI2C0_S)
PTA3: J25.12(B6) SH12.1 U17.72(PTA3/ADC1_SE1/FTM3_CH1/LPI2C0_S)
PTA4: J3.16(B8) R122.1 U17.98(PTA4/ACMP0_OUT/E\W\M\_\O\U\T\/J)
PTA6: R147.2 R174.2 U17.58(PTA6/ADC0_SE2/ACMP1_IN0/FTM0_FL)
PTA7: J25.8(B4) SH8.2 U17.57(PTA7/ADC0_SE3/ACMP1_IN1/FTM0_FL)
PTA8: J6.17 U17.100(PTA8/LPUART3_RX/LPSPI2_SOUT/FXI)
PTA9: J6.19 U17.99(PTA9/LPUART3_TX/LPSPI2_PCS0/FXI)
PTA10: J3.14(B7) R123.1 U17.92(PTA10/FTM1_CH4/FXIO_D0/JTAG_TDO)
PTA11: J1.2(B1) U17.91(PTA11/FTM1_CH5/FXIO_D1)
PTA12: J6.16 U17.90(PTA12/FTM1_CH6/CAN1_RX/LPI2C1_S)
PTA13: J6.14 U17.89(PTA13/FTM1_CH7/CAN1_TX/LPI2C1_S)
PTA14: J2.16 U17.88(PTA14/FTM0_FLT0/FTM3_FLT1/EWM_I)
PTA15: R167.1 U17.83(PTA15/ADC1_SE12/FTM1_CH2/LPSPI0)
PTA16: R165.1 U17.82(PTA16/ADC1_SE13/FTM1_CH3/LPSPI1)
PTA17: J1.4(B2) U17.62(PTA17/FTM0_CH6/FTM3_FLT0/E\W\M\)
PTB0: R175.2 SH5.1 U17.54(PTB0/ADC0_SE4/LPUART0_RX/LPSPI0)
PTB1: R176.2 SH4.1 U17.53(PTB1/ADC0_SE5/LPUART0_TX/LPSPI0)
PTB2: J2.11 U17.48(PTB2/ADC0_SE6/FTM1_CH0/LPSPI0_S)
PTB3: J2.9 U17.47(PTB3/ADC0_SE7/FTM1_CH1/LPSPI0_S)
PTB4: J2.7 U17.28(PTB4/ACMP1_IN2/FTM0_CH4/LPSPI0_)
PTB5: J2.5 U17.27(PTB5/FTM0_CH5/LPSPI0_PCS1/TRGMU)
PTB6: R81.2 R84.1 U17.16(PTB6/LPI2C0_SDA)
PTB6_XTAL: C127.1 R84.2 R91.2 Y3.2
PTB7: R88.1 R90.2 U17.15(PTB7/LPI2C0_SCL)
PTB7_EXTAL: C126.1 R88.2 R91.1 Y3.1
PTB8: J1.5(A3) U17.77(PTB8/FTM3_CH0)
PTB9: J1.7(A4) U17.76(PTB9/FTM3_CH1/LPI2C0_SCLS)
PTB10: J1.9(A5) U17.75(PTB10/FTM3_CH2/LPI2C0_SDAS)
PTB11: J1.11(A6) U17.74(PTB11/FTM3_CH3/LPI2C0_HREQ)
PTB12: R180.2 SH15.1 U17.68(PTB12/ADC1_SE7/FTM0_CH0/FTM3_FL)
PTB13: J25.16(B8) SH16.2 U17.67(PTB13/ADC1_SE8/FTM0_CH1/FTM3_FL)
PTB14: J4.8(B4) R124.1 U17.66(PTB14/ADC1_SE9/FTM0_CH2/LPSPI1_)
PTB15: J4.10(B5) R125.1 U17.65(PTB15/ADC1_SE14/FTM0_CH3/LPSPI1)
PTB16: J4.12(B6) R126.1 U17.64(PTB16/ADC1_SE15/FTM0_CH4/LPSPI1)
PTB17: J4.6(B3) R129.2 U17.63(PTB17/FTM0_CH5/LPSPI1_PCS3)
PTC0: R146.2 U17.40(PTC0/ADC0_SE8/ACMP1_IN4/FTM0_CH)
PTC1: J5.13 U17.39(PTC1/ADC0_SE9/ACMP1_IN3/FTM0_CH)
PTC2: J5.15 U17.30(PTC2/ADC0_SE10/ACMP0_IN5/FTM0_C)
PTC3: J4.16(B8) R132.2 R163.1 U17.29(PTC3/ADC0_SE11/ACMP0_IN4/FTM0_C)
PTC4: J3.12(B6) R127.1 U17.96(PTC4/FTM1_CH0/RTC_CLKOUT/EWM_IN)
PTC5: J3.10(B5) R128.1 U17.95(PTC5/FTM2_CH0/RTC_CLKOUT/LPI2C1)
PTC6: J4.4(B2) R161.1 U17.81(PTC6/ADC1_SE4/LPUART1_RX/CAN1_R)
PTC7: J4.2(B1) R162.1 U17.80(PTC7/ADC1_SE5/LPUART1_TX/CAN1_T)
PTC8: J6.9 U17.56(PTC8/LPUART1_RX/FTM1_FLT0/LPUAR)
PTC9: J6.11 U17.55(PTC9/LPUART1_TX/FTM1_FLT1/LPUAR)
PTC10: R133.2 U17.52(PTC10/FTM3_CH4/TRGMUX_IN11)
PTC11: R134.2 U17.51(PTC11/FTM3_CH5/TRGMUX_IN10)
PTC12: J2.10 R152.1 U17.50(PTC12/FTM3_CH6/FTM2_CH6/LPUART3)
PTC13: J2.12 R153.1 U17.49(PTC13/FTM3_CH7/FTM2_CH7/LPUART3)
PTC14: J4.14(B7) R164.1 U17.46(PTC14/ADC0_SE12/FTM1_CH2/TRGMUX)
PTC15: J5.20 U17.45(PTC15/ADC0_SE13/FTM1_CH3/TRGMUX)
PTC16: J6.8 U17.44(PTC16/ADC0_SE14/FTM1_FLT2/CAN2_)
PTC17: J6.6 U17.43(PTC17/ADC0_SE15/FTM1_FLT3/CAN2_)
PTD0: J2.6 J6.1 R156.1 U17.4(PTD0/FTM0_CH2/LPSPI1_SCK/FTM2_C)
PTD1: J6.2 U17.3(PTD1/FTM0_CH3/LPSPI1_SIN/FTM2_C)
PTD2: J25.13(A7) SH13.2 U17.71(PTD2/ADC1_SE2/FTM3_CH4/LPSPI1_S)
PTD3: J1.14(B7) J6.4 U17.70(PTD3/ADC1_SE3/FTM3_CH5/LPSPI1_P)
PTD4: R179.2 SH14.1 U17.69(PTD4/ADC1_SE6/FTM0_FLT3/FTM3_FL)
PTD5: J1.12(B6) U17.33(PTD5/FTM2_CH3/LPTMR0_ALT2/FTM2_)
PTD6: J5.18 R130.2 U17.32(PTD6/ACMP0_IN7/LPUART2_RX/FTM2_)
PTD7: J5.16 R131.2 U17.31(PTD7/ACMP0_IN6/LPUART2_TX/FTM2_)
PTD8: J6.7 U17.42(PTD8/LPI2C1_SDA/FTM2_FLT2/FTM1_)
PTD9: J6.5 U17.41(PTD9/LPI2C1_SCL/FTM2_FLT3/FTM1_)
PTD10: J1.6(B3) R166.1 U17.36(PTD10/FTM2_CH0/FTM2_QD_PHB)
PTD11: J1.8(B4) R168.1 U17.35(PTD11/FTM2_CH1/FTM2_QD_PHA/LPUA)
PTD12: J1.10(B5) U17.34(PTD12/FTM2_CH2/LPI2C1_HREQ/LPUA)
PTD13: J2.1 U17.25(PTD13/FTM2_CH4/LPUART3_RX/RTC_C)
PTD14: J2.3 U17.24(PTD14/FTM2_CH5/LPUART3_TX/CLKOU)
PTD15: J2.2 R154.1 U17.22(PTD15/FTM0_CH0/HDPIN)
PTD16: J2.4 R155.1 U17.21(PTD16/FTM0_CH1/HDPIN)
PTD17: J6.13 U17.20(PTD17/FTM0_FLT2/LPUART2_RX)
PTE0: J2.19 U17.94(PTE0/LPSPI0_SCK/TCLK1/LPI2C1_SD)
PTE1: J2.17 U17.93(PTE1/LPSPI0_SIN/LPI2C0_HREQ/LPI)
PTE2: R145.2 U17.85(PTE2/ADC1_SE10/LPSPI0_SOUT/LPTM)
PTE3: J1.16(B8) U17.18(PTE3/FTM0_FLT0/LPUART2_RTS/FTM2)
PTE4: J6.20 R137.2 U17.9(PTE4/BUSOUT/FTM2_QD_PHB/FTM2_CH)
PTE5: J6.18 R136.2 U17.8(PTE5/TCLK2/FTM2_QD_PHA/FTM2_CH3)
PTE6: R144.2 U17.84(PTE6/ADC1_SE11/LPSPI0_PCS2/FTM3)
PTE7: J2.14 U17.59(PTE7/FTM0_CH7/FTM3_FLT0)
PTE8: J2.8 R135.2 U17.26(PTE8/ACMP0_IN3/FTM0_CH6)
PTE9: J3.8(B4) U17.23(PTE9/FTM0_CH7/LPUART2_CTS)
PTE10: J3.6(B3) U17.6(PTE10/CLKOUT/LPSPI2_PCS1/FTM2_C)
PTE11: J5.14 U17.5(PTE11/LPTMR0_ALT1/FTM2_CH5/FXIO)
PTE12: J6.15 R159.2 U17.19(PTE12/FTM0_FLT3/LPUART2_TX)
PTE13: J5.8 U17.7(PTE13/LPSPI2_PCS2/FTM2_FLT0)
PTE14: J5.6 U17.17(PTE14/FTM0_FLT1/FTM2_FLT1)
PTE15: J5.4 U17.2(PTE15/LPUART3_CTS/LPSPI2_SCK/FT)
PTE16: J5.2 U17.1(PTE16/LPUART3_RTS/LPSPI2_SIN/FT)
PWR_LED: D3.A(ANODE) R56.1
RGB_BLUE: R95.2 R156.2
RGB_GREEN: R96.2 R155.2
RGB_RED: R97.2 R154.2
RST_TGTMCU_B: D1.C(CATHODE) J3.5(A3) J14.10(B5) J104.3 R4.2 R5.2 R102.1 U1.7(B1) U17.97(PTA5/TCLK1/J\T\A\G\_\T\R\S\T\/R)
SBC_CAN_RX: R137.1 TP20.1(PIN1) U19.31(RXD)
SBC_CAN_TX: R136.1 TP21.1(PIN1) U19.30(TXD)
SBC_CANH: L4.1(IN1) U19.7(CANH)
SBC_CANL: L4.3(OUT1) U19.8(CANL)
SBC_CS: R129.1 TP33.1(PIN1) U19.25(C\S\)
SBC_DBG: R104.2 R105.2 TP26.1(PIN1) U19.13(DBG)
SBC_DBG_8V2: D8.C(CATHODE) R105.1 R113.2
SBC_DBG_GND: R104.1 R108.1
SBC_INT: R93.1 R159.1
SBC_IO-0: C46.1 R116.2 U19.12(I/O-0)
SBC_LIN-T1: D6.A U19.4(LIN-T/I/O-2)
SBC_LIN_RX: R130.1 TP35.1(PIN1) U19.21(RXD-L)
SBC_LIN_TX: R131.1 TP37.1(PIN1) U19.20(TXD-L)
SBC_MISO: R125.2 TP23.1(PIN1) U19.28(MISO)
SBC_MOSI: R126.2 TP25.1(PIN1) U19.27(MOSI)
SBC_MUX: C44.1 R112.2 R163.2
SBC_RST: R102.2 TP24.1(PIN1) U19.23(R\S\T\)
SBC_SAFE: R73.2 R75.2 U19.5(SAFE)
SBC_SCK: R124.2 TP27.1(PIN1) U19.26(SCLK)
SBC_SPLIT: R100.2 U19.10(SPLIT)
SBC_VB: Q1.3(BASE) U19.1(VB)
SBC_VDD: C27.1 J107.1 Q1.2(COLLECTOR) TP15.1(PIN1) U19.29(VDD)
SBC_VE: Q1.1(EMITTER) U19.32(VE)
SBC_VSENSE: C42.1 R110.2 U19.22(VSENSE)
SDA_EXTAL: C23.1 U8.17(EXTAL0/PTA18/FTM0_FLT2/FTM_CLKI) Y1.3
SDA_JTAG_TCLK: J12.4(B2) U8.12(JTAG_TCLK/SWD_CLK/EZP_CLK/TSI0_)
SDA_JTAG_TDI: J12.8(B4) U8.13(JTAG_TDI/EZP_DI/TSI0_CH2/PTA1/U)
SDA_JTAG_TDO: J12.6(B3) U8.14(JTAG_TDO/TRACE_SWO/EZP_DO/TSI0_)
SDA_JTAG_TMS: J12.2(B1) R77.2 U8.15(JTAG_TMS/SWD_DIO/TSI0_CH4/PTA3/)
SDA_LED: D2.C(CATHODE) U8.29(PTD4/SPI0_PCS1/U\A\R\T\0\_\R\T\)
SDA_LED_R: D2.A(ANODE) R12.2
SDA_RST: J12.10(B5) R57.2 R62.1 TP12.1(PIN1) U8.19(R\E\S\E\T\)
SDA_RST_LED: D1.A(ANODE) R2.1
SDA_RST_TGTMCU_B: J105.2 U8.21(ADC0_SE9/TSI0_CH6/PTB1/I2C0_SDA)
SDA_RST_TGTMCU_J_B: J104.1 J105.1 R3.2 R5.1 U1.2(A1)
SDA_RX_EN: R15.2 R16.1 U4.5(DIR)
SDA_SPI0_CS: R38.2 TP7.1(PIN1) U8.23(ADC0_SE4B/CMP1_IN0/TSI0_CH15/PT)
SDA_SPI0_RST_B: R41.2 TP8.1(PIN1) U8.22(ADC0_SE15/TSI0_CH14/PTC1/SPI0_P)
SDA_SPI0_SCK: U8.26(PTC5/SPI0_SCK/LPTMR0_ALT2/I2S0_) U10.3(A)
SDA_SPI0_SIN: U2.5(2A) U8.28(CMP0_IN1/PTC7/SPI0_SIN/USB_SOF_)
SDA_SPI0_SOUT: U7.3(A) U8.27(CMP0_IN0/PTC6/SPI0_SOUT/PDB0_EX)
SDA_SWD_EN: R41.1 R47.1 U9.6(Y\1\)
SDA_SWD_EN_B: R49.2 U8.16(N\M\I\/E\Z\P\_\C\S\/TSI0_CH5/PT)
SDA_SWD_EN_B_R: R42.2 R49.1 U9.1(A1)
SDA_SWD_EN_R: R47.2 R51.1 R52.2 U10.5(DIR)
SDA_SWD_OE: R35.1 R38.1 U9.4(Y\2\)
SDA_SWD_OE_B: R32.2 U8.20(ADC0_SE8/TSI0_CH0/PTB0/I2C0_SCL)
SDA_SWD_OE_B_R: R32.1 R39.1 U9.3(A2)
SDA_SWD_OE_R: R30.2 R31.1 R35.2 U7.5(DIR)
SDA_USB_CONN_DN: J7.2(D-) R25.1 U5.1(A1)
SDA_USB_CONN_DP: J7.3(D+) R21.1 U3.1(A1)
SDA_USB_DN: R25.2 U8.4(USB0_DM)
SDA_USB_DP: R21.2 U8.3(USB0_DP)
SDA_USB_P5V_SENSE: R14.2 R20.1 U8.30(ADC0_SE6B/PTD5/SPI0_PCS2/U\A\R\)
SDA_USBSHIELD: J7.6(SHELL1) J7.7(SHELL2) J7.8(SHELL3) J7.9(SHELL4) J7.10(SHELL5) L2.1
SDA_VOUT33: C9.1 J9.2 U8.5(VOUT33)
SDA_XTAL: C20.1 U8.18(XTAL0/PTA19/FTM1_FLT0/FTM_CLKIN) Y1.1
SPLIT: C40.1 R92.2 R98.2 R100.1
SW1_RST_B: C1.1 J104.2 SW5.2 SW5.4
SWD_CLK_TGTMCU_BUF: J8.1 U10.4(B)
SWD_DIO_TGTMCU_BUF: J106.1 U2.2(2B) U7.4(B)
TC_EXTAL_TP: TP11.1(PIN1) U8.10(EXTAL32)
TC_SDA_USB_ID_TP: J7.4(ID) TP6.1(PIN1)
TC_XTAL_TP: TP10.1(PIN1) U8.9(XTAL32)
TP_2102_A: TP500.1(PIN1) U1.3(A2)
TP_2102_B: TP501.1(PIN1) U1.6(B2)
UART1_RX_TGTMCU_BUF: R24.1 U4.4(B)
UART1_RX_TGTMCU_R: U4.3(A) U8.25(PTC4/SPI0_PCS0/UART1_TX/FTM0_CH)
UART1_TX_TGTMCU_BUF: R18.1 U2.1(1B)
UART1_TX_TGTMCU_R: U2.6(1A) U8.24(CMP1_IN1/PTC3/SPI0_PCS1/UART1_R)
UART_RX: R24.2 R161.2
UART_TX: R18.2 R162.2
V_TGTMCU: C2.1 C4.1 C8.1 R2.2 R4.1 SH1.1 U1.8(VCCB) U2.8(VCCB) U4.6(VCCB) U7.6(VCCB) U10.6(VCCB)
VCAN: C30.1 C31.1 U19.6(5V-CAN)
VREFH: C148.1 D7.C(CATHODE) R99.2 R103.2 R109.1 U17.12(VREFH)
VSUP: C29.1 C47.1 C128.1 D9.C D13.C R113.1 R118.1 TP36.1(PIN1) U19.2(VSUP1)
VTRG_EN: R68.1 R69.2 R70.2 U11.3(ENABLE)
VTRG_FAULT_B: R60.2 U8.32(PTD7/CMT_IRO/UART0_TX/FTM0_CH7/) U11.4(F\A\U\L\T\)
N20081740: D4.C(CATHODE) R73.1
N20083007: R107.1 R112.1 U19.11(MUX-OUT)
N20177646: J5.19 R75.1
N20181172: R116.1 R118.2 SW6.2 SW6.4
N20279148: J3.2(B1) R81.1
N20279153: J3.4(B2) R90.1
N20335552: J14.6(B3) R119.1
N20335572: J14.8(B4) R120.1
N20337946: J5.3 R165.2 R166.2
N20338949: J5.1 R167.2 R168.2
N20340033: J5.9 SH8.1
N20340042: J5.11 SH16.1
N20340793: J6.3 SH13.1
N20341595: J1.13(A7) R132.1 R133.1
N20341806: J1.15(A8) R134.1 R135.1
N20342136: J5.5 SH10.1
N20342745: J5.7 SH9.1
N20344624: J4.15(A8) R140.2 R144.1
N20344681: J4.13(A7) R141.2 R145.1
N20344687: J4.11(A6) R142.2 R146.1
N20344693: J4.9(A5) R143.2 R147.1
N20362140: R93.2 U19.24(I\N\T\)
N20408163: R169.2 R170.2 U15.3(EN)
N20408770: C59.1 U15.4(BYP)
N20435841: J4.7(A4) SH4.2
N20435866: J4.5(A3) SH5.2
N20437402: J1.3(A2) SH12.2
N20437406: J1.1(A1) SH11.2
N20438625: J4.3(A2) SH15.2
N20438629: J4.1(A1) SH14.2

Pads without a net: J2 18 20; J5 17; J11 3; J12 7 9; J13 3; J14 7 9; J25 2 17 18 20; U19 3 14 16 17

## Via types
v1: diameter 0.508, hole 0.254, TOP to BOTTOM, 461 vias
v2: diameter 0.61, hole 0.356, TOP to BOTTOM, 24 vias
v3: diameter 1.016, hole 0.711, TOP to BOTTOM, 2 vias
v4: diameter 0.457, hole 0.203, TOP to BOTTOM, 352 vias

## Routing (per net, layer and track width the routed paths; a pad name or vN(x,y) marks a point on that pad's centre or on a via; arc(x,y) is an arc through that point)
GND: length 880.4
  TOP w0.203: U1.4 7.34,52.59 v1(7.11,52.82)
  TOP w0.254: SW6.3 2.24,11.67 ; SW6.3 3.18,10.98 ; SW6.3 3.18,11.6 ; SW6.3 1.3,10.36 ; SW6.3 1.3,10.98 ; SW6.3 2.24,10.3 ; 29.02,15.53 U19.15 31,15.67 ; R13.3 102.54,43.31 ; R13.3 102.78,42.52 ; R13.3 101.76,43.54 ; R13.3 100.98,41.74 ; R13.3 102.54,41.74 ; R13.3 101.76,41.51 ; R13.3 100.98,43.31 ; R13.3 100.74,42.52 ; R44.2 100.85,40.13 ; R44.2 100.42,39.2 ; R44.2 100.34,39.63 ; R44.2 101.27,40.05 ; R44.2 100.42,40.05 ; R44.2 101.35,39.63 ; J16.2 13.69,11.8 ; J16.2 14.6,11.8 ; J16.2 14.6,9.88 ; J16.2 12.77,9.88 ; J16.2 12.77,11.8 ; J16.2 12.77,7.96 ; J16.2 13.69,7.96 ; J16.2 14.6,7.96 ; U19.33 37.43,19.89 ; U19.33 32.07,19.89 ; U19.33 34.75,22.57 ; U19.33 32.07,22.57 ; U19.33 32.07,17.21 ; U19.33 34.75,17.21 ; U11.2 9.43,33.83 ; U11.2 8.63,33.83 ; U11.2 9.43,32.23 ; U11.2 9.03,32.23 ; TP1.1 99.29,56.68 ; TP1.1 100.02,56.47 ; TP1.1 98.33,55.73 ; TP1.1 98.55,56.47 ; TP1.1 100.02,54.99 ; TP1.1 100.24,55.73 ; TP1.1 98.55,54.99 ; TP1.1 99.29,54.78 ; 6.45,14.89 TP32.1 ; TP32.1 6.24,15.63 ; TP32.1 6.45,16.37 ; TP32.1 7.93,16.37 ; TP32.1 7.93,14.89 ; TP32.1 7.19,16.58 ; TP32.1 8.14,15.63 ; TP32.1 7.19,14.68 ; C19.2 32.03,36.54 ; C19.2 31.6,36.45 ; C19.2 32.45,36.45 ; C19.2 31.6,35.6 ; C19.2 32.45,35.6 ; C19.2 32.54,36.03 ; 77.91,56.71 J6.12 ; J6.12 77.91,55.13 ; J6.12 79.49,55.13 ; J6.12 78.7,54.89 ; J6.12 79.73,55.92 ; J6.12 79.49,56.71 ; J6.12 77.67,55.92 ; 2.04,16.4 J13.4 ; J13.4 3.6,16.4 ; J13.4 2.82,16.63 ; J13.4 2.82,14.6 ; J13.4 3.6,14.83 ; J13.4 1.81,15.62 ; J13.4 3.84,15.62 ; J13.4 2.04,14.83 ; 57.59,27.2 C127.2 ; C127.2 57.68,27.63 ; C127.2 58.1,27.71 ; C127.2 58.61,27.2 ; C127.2 58.52,27.63 ; SW5.3 6.94,55.97 ; SW5.3 5.05,55.35 ; SW5.3 5.99,56.66 ; SW5.3 6.94,56.59 ; SW5.3 5.05,55.97 ; SW5.3 5.99,55.29 ; 8.93,39.85 C11.2 ; C11.2 8.85,40.28 ; C11.2 8.93,40.7 ; C11.2 9.78,39.85 ; C11.2 9.78,40.7 ; C11.2 9.35,40.79 ; L2.2 6.81,39.31 ; L2.2 5.62,38.42 ; L2.2 6.21,39.36 ; L2.2 5.62,39.31 ; L2.2 6.21,38.37 ; U2.4 29.3,48.37 ; U2.4 28.79,48.37 ; U2.4 v1(29.05,48.61) ; 9.55,29.4 C25.2 ; C25.2 10.48,29.82 ; C25.2 10.4,30.25 ; C25.2 9.98,30.33 ; C25.2 9.55,30.25 ; C25.2 10.4,29.4 ; C40.2 14.95,15.21 ; C40.2 13.43,15.21 ; C40.2 13.43,15.84 ; C146.2 88.2,27.03 ; C146.2 88.2,26.39 ; C146.2 86.67,27.03 ; C146.2 86.67,26.39 ; C146.2 87.43,26.39 ; 56.71,36.13 C131.2 ; C131.2 56.71,36.89 ; C131.2 57.35,36.13 ; C131.2 56.71,37.66 ; 39.81,5.91 J3.11 ; J3.11 41.39,5.91 ; J3.11 39.81,4.33 ; J3.11 41.63,5.12 ; J3.11 41.39,4.33 ; J3.11 39.57,5.12 ; 38.09,8.02 C128.2 ; C128.2 38.73,9.54 ; C128.2 38.73,8.02 ; C128.2 38.09,9.54 ; C16.2 101.27,36.93 ; C16.2 101.27,36.09 ; C16.2 101.35,36.51 ; C16.2 100.42,36.93 ; C16.2 100.42,36.09 ; C16.2 100.34,36.51 ; 10.2,55.35 SW5.1 ; SW5.1 11.15,56.66 ; SW5.1 12.09,55.97 ; SW5.1 11.15,55.29 ; SW5.1 12.09,56.59 ; SW5.1 10.2,55.97 ; C145.2 64.09,33.8 ; C145.2 63.24,34.64 ; C145.2 64.18,34.22 ; C145.2 63.16,34.22 ; C145.2 63.67,34.73 ; C145.2 64.09,34.64 ; R31.2 32.46,41.75 ; R31.2 31.61,41.75 ; R31.2 31.61,42.6 ; R31.2 32.46,42.6 ; R31.2 32.03,42.69 ; D8.A 22.28,12.66 ; D8.A 22.31,13.48 ; D8.A 21.62,14.31 ; D8.A 21.62,12.66 ; D8.A 20.95,14.31 ; D8.A 20.95,12.66 ; C28.2 101.27,21.44 ; C28.2 100.85,22.38 ; C28.2 101.35,21.87 ; C28.2 100.42,22.29 ; C28.2 101.27,22.29 ; C28.2 100.42,21.44 ; C26.2 19.75,29.53 ; C26.2 18.82,29.11 ; C26.2 19.75,28.69 ; C26.2 18.91,28.69 ; C26.2 18.91,29.53 ; 76.39,39.05 C142.2 ; C142.2 76.21,39.17 ; C142.2 76.63,38.92 76.37,38.66 U17.86 ; 22.55,34.46 Y1.2 ; Y1.2 23.15,33.3 ; Y1.2 24.31,32.7 ; Y1.2 23.71,33.86 ; 15.5,14.98 C44.2 ; C44.2 15.5,13.46 ; C44.2 16.14,13.46 ; 97.27,46.5 C5.2 ; C5.2 97.27,45.66 ; C5.2 97.69,46.59 ; C5.2 98.11,46.5 ; C5.2 98.11,45.66 ; C5.2 97.18,46.08 ; 29.02,19.43 U19.9 31,19.57 ; 10.91,29.63 R68.2 ; R68.2 11.75,29.63 ; R68.2 10.82,30.05 ; R68.2 11.75,30.47 ; R68.2 10.91,30.47 ; R68.2 11.84,30.05 ; 4.52,49.12 C4.2 ; C4.2 4.1,49.2 ; C4.2 4.94,49.2 ; C4.2 4.94,50.05 ; 21.29,29.32 TP17.1 ; TP17.1 21.29,27.85 ; TP17.1 22.98,28.59 ; TP17.1 22.03,29.54 ; TP17.1 22.77,29.32 ; TP17.1 21.08,28.59 ; TP17.1 22.03,27.63 ; TP17.1 22.77,27.85 ; D3.C 38.12,11.91 ; D3.C 37.51,11.32 ; D3.C 36.9,11.33 ; D3.C 38.12,11.33 ; 18.48,45.05 C6.2 ; C6.2 17.97,45.56 ; C6.2 18.9,45.13 ; C23.2 22.15,34.67 ; C23.2 21.14,34.67 ; C23.2 21.64,34.16 ; C23.2 21.64,35.18 ; J12.5 17.85,30.1 ; J12.5 17.85,31.17 ; J12.5 17.99,30.63 ; J16.SH1 13.7,2.58 ; J16.SH1 12.79,4.64 ; J16.SH1 11.87,2.58 ; J16.SH1 13.7,4.64 ; C141.2 74.61,19.51 74.87,19.77 U17.37 ; C141.2 75.03,19.36 ; C141.2 74.1,18.94 ; C141.2 74.19,18.52 ; 32.03,36.61 R51.2 ; R51.2 32.46,36.69 ; R51.2 32.46,37.54 ; R51.2 31.61,36.69 ; 58.1,28.09 C126.2 ; C126.2 57.59,28.6 ; C126.2 58.61,28.6 ; C126.2 58.52,28.18 ; C126.2 57.68,28.18 ; 85.19,26.95 C143.2 ; C143.2 85.19,27.8 ; C143.2 86.12,27.37 ; C143.2 85.62,26.87 ; C143.2 86.04,27.8 ; C143.2 84.91,27.37 84.63,27.66 U17.60 ; C143.2 86.04,26.95 ; C7.2 19.78,44.24 ; C7.2 19.36,44.16 ; C7.2 19.78,45.09 ; C7.2 18.85,44.67 ; v1(68.92,28.37) 68.64,28.66 U17.14 ; C18.2 28.41,36.54 ; C18.2 27.98,36.45 ; C18.2 27.98,35.6 ; C18.2 27.9,36.03 ; 26.33,36.04 R62.2 ; R62.2 27.26,36.47 ; R62.2 26.84,35.54 ; R62.2 27.35,36.04 ; R62.2 26.84,36.55 ; C140.2 63,34.64 ; C140.2 62.07,34.22 ; C140.2 62.58,34.73 ; C140.2 62.15,33.8 ; C140.2 62.15,34.64 ; C140.2 63.08,34.22 ; 45.51,28.87 R170.1 45.63,29.54 ; J2.13 26.38,54.41 ; J2.13 25.59,52.59 ; J2.13 27.17,52.59 ; J2.13 25.59,54.17 ; J2.13 26.38,52.35 ; J2.13 25.35,53.38 ; J2.13 27.17,54.17 ; 11.29,52.01 C1.2 ; C1.2 12.14,52.01 ; C1.2 11.71,51.92 ; C1.2 11.29,52.85 ; 66.6,28.66 U17.14 ; U17.14 66.6,28.56 ; U6.2 9.32,41.98 ; U6.2 8.68,41.94 ; U6.2 9.32,40.9 ; U6.2 9.96,40.94 ; U6.2 9.96,41.94 ; U6.2 8.68,40.94 ; C144.2 61.48,34.73 ; C144.2 61.99,34.22 ; C144.2 60.97,34.22 ; C144.2 61.91,34.64 ; C144.2 61.06,34.64 ; C144.2 61.91,33.8 ; 6.45,10.36 SW6.1 ; SW6.1 8.33,10.98 ; SW6.1 7.39,10.3 ; SW6.1 7.39,11.67 ; SW6.1 6.45,10.98 ; SW6.1 8.33,11.6 ; 85.29,2.58 J5.12 ; J5.12 86.32,3.61 ; J5.12 87.35,2.58 ; J5.12 87.11,1.79 ; J5.12 85.53,1.79 ; J5.12 86.32,1.55 ; J5.12 85.53,3.37 ; J5.12 87.11,3.37 ; U8.2 v1(18.1,42.9) ; C8.2 28.33,43.28 ; C8.2 28.75,43.2 ; C8.2 28.75,42.35 ; C8.2 27.9,43.2 ; C8.2 28.33,42.27 ; J16.SH2 23.6,4.64 ; J16.SH2 22.69,4.64 ; J16.SH2 21.77,2.58 ; J16.SH2 23.6,2.58 ; J16.SH2 21.77,4.64 ; 56.71,35.22 C129.2 56.71,35.98 ; 21.7,43.88 R20.2 ; R20.2 21.28,43.96 ; R20.2 21.19,44.39 ; J3.13 44.17,5.12 ; J3.13 42.11,5.12 ; J3.13 42.35,5.91 ; J3.13 43.93,4.33 ; J3.13 42.35,4.33 ; C2.2 1.91,52.42 ; C2.2 1.49,52.62 v1(1.62,52.75) ; C2.2 1.73,52.54 ; 66.6,29.06 U17.13 ; U17.13 v1(68.93,29.16) ; U17.13 66.6,29.16 ; U8.8 v1(16.16,39.75) ; 95.83,31.93 J25.6 ; J25.6 95.83,32.76 ; J25.6 97.48,31.79 ; J25.6 95.83,32.35 ; J25.6 99.13,32.76 ; J25.6 97.48,32.91 ; C17.2 6.28,37.97 ; C17.2 4.75,37.97 ; C17.2 5.51,37.97 ; C17.2 6.28,37.34 ; 53.74,32.22 C148.2 ; C148.2 54.37,32.22 ; C148.2 54.37,30.69 ; 100.85,18.18 R74.2 ; R74.2 100.42,19.11 ; R74.2 100.34,18.68 ; R74.2 100.42,18.26 ; R74.2 101.27,19.11 ; R74.2 101.27,18.26 ; 46.63,28.99 U15.2 48,29.23 ; 13.56,38.99 C12.2 ; C12.2 13.56,38.36 ; C12.2 14.32,38.36 ; U7.2 v1(27.8,41.16) ; 82.1,27.66 U17.60 ; U17.60 82.1,27.56 ; 56.71,41.83 C147.2 ; C147.2 56.71,40.3 ; C147.2 56.71,41.06 ; U10.2 27.95,38.12 v1(27.7,37.88) ; J16.3 19.8,7.96 ; J16.3 17.97,7.96 ; J16.3 17.97,9.88 ; J16.3 18.89,7.96 ; J16.3 19.8,11.8 ; J16.3 19.8,9.88 ; J16.3 17.97,11.8 ; J16.3 18.89,11.8 ; C3.2 11.23,49.94 ; C3.2 11.14,50.37 ; C3.2 v1(10.72,50.76) ; C3.2 10.3,50.37 ; 7.05,51.91 U1.4 7.18,52.46 ; J11.4 3.6,27.41 ; J11.4 1.81,28.19 ; J11.4 2.82,29.21 ; J11.4 2.82,27.18 ; J11.4 2.04,27.41 ; J11.4 3.84,28.19 ; J11.4 3.6,28.98 ; J11.4 2.04,28.98 ; 76.37,35.89 U17.86 ; U17.86 76.28,35.89 ; 21.44,15.44 R108.2 21.44,14.68 ; U9.2 v1(36.02,39.65) ; 26.77,26.28 C29.2 ; C29.2 28.3,25.64 ; C29.2 27.53,26.28 ; C29.2 28.3,26.28 ; U2.3 29.65,48.31 v1(29.84,48.5) ; U2.3 30.07,48.11 ; U2.3 30.07,47.85 ; 35.93,11.15 C47.2 35.3,11.15 ; 92.4,23.04 J25.19 ; J25.19 92.4,23.46 ; J25.19 95.7,23.46 ; J25.19 95.7,23.87 ; J25.19 92.4,23.87 ; J25.19 94.05,24.02 ; C20.2 22.83,35.37 ; C20.2 22.32,35.88 ; C20.2 22.32,34.86 ; C20.2 21.81,35.37 ; 8.68,42.44 U5.2 ; U5.2 9.32,42.4 ; U5.2 9.96,42.44 ; 31.61,45.87 R16.2 ; R16.2 32.46,45.02 ; R16.2 32.46,45.87 ; R16.2 31.61,45.02 ; R16.2 32.03,45.96 ; U17.37 74.87,22.42 ; U17.37 74.78,20.39 ; 44.91,16.9 C42.2 44.91,15.38 ; 74.48,15.52 C137.2 ; C137.2 76,15.52 ; C137.2 74.48,14.88 ; C137.2 76,14.88 ; 56.71,37.81 C43.2 ; C43.2 56.71,39.33 ; C43.2 56.71,38.57 ; 38.21,41.04 C10.2 38.38,40.92 ; 75.35,43.03 C133.2 ; C133.2 75.35,43.67 ; C133.2 76.87,43.03 ; C133.2 76.87,43.67 ; U4.2 v1(27.85,44.44) ; 17.99,29.36 J12.3 17.85,29.9 ; 22.46,23.38 C30.2 22.46,23.7 ; J14.5 53.83,41.83 ; J14.5 53.7,42.37 ; J14.5 53.7,41.29 ; 38.51,15.53 U19.18 38.51,15.67 ; 15.5,16.51 R107.2 ; R107.2 15.5,14.98 ; R107.2 16.14,16.51 ; 53.16,33.28 D7.A ; D7.A 53.21,33.89 ; D7.A 53.67,33.89 ; D7.A 54.13,33.89 ; D7.A 54.18,33.28 ; D7.A 53.21,32.67 ; C9.2 14.97,43.38 ; C9.2 13.44,42.76 ; C9.2 14.52,43.83 ; C9.2 13.89,42.31 ; 42.12,27.67 C22.2 ; C22.2 41.36,27.67 ; C22.2 42.88,27.67 ; C22.2 42.88,28.31 ; 3.28,45.58 J7.5 3.28,45.32 ; 29.15,31.99 C27.2 ; C27.2 29.79,31.99 ; C27.2 29.79,30.47 ; C27.2 29.15,30.47 ; U3.2 9.96,44.95 ; U3.2 8.68,44.95 ; U3.2 9.32,45 ; 53.83,40.56 J14.3 53.7,41.1 ; 32.6,7.22 C49.2 31.65,7.22 ; 39.54,27.67 C21.2 ; C21.2 41.07,27.67 ; C21.2 40.3,27.67 ; 11.32,13.13 C46.2 11.01,13.13
  TOP w0.356: U19.9 28.63,19.57 v1(28.63,19.57)
  TOP w0.381: v1(48.01,26.47) 48.19,26.65 C59.2 ; J7.5 v1(5.41,45.32) ; U19.18 40.68,15.67 v1(40.84,15.51)
  TOP w0.406: U19.15 v1(28.65,15.67)
  TOP w0.508: J25.6 v1(99.61,32.35) ; C11.2 v1(10.16,40.28) ; J25.19 v1(94.05,22.52) ; v1(22.46,14.42) 22.08,14.8 R108.2 ; R20.2 v1(21.15,44.93) ; C9.2 v1(13.79,43.48) ; L2.2 v1(5.04,38.87) ; C7.2 20.08,44.67 v1(20.11,44.7) ; U3.2 v1(10.32,44.46) ; U5.2 v1(10.27,42.94) ; R62.2 27.45,35.43 v1(27.45,35.05) ; C10.2 v1(38.63,40.69) ; R107.2 v1(15.21,15.75) ; C16.2 v1(100.84,35.61) ; R170.1 45.98,29.29 v2(46.04,29.23) ; C46.2 v1(12.32,13.89) ; C17.2 v1(4.37,37.34) ; C40.2 v1(14.19,14.95) ; R31.2 v1(32.94,42.18) ; C128.2 v2(37.72,8.78) ; C6.2 v1(19.27,45.56) ; C18.2 v1(28.41,35.09) ; R68.2 v1(11.33,29.08) ; v4(33.04,7.98) C49.2 ; C5.2 v1(98.73,46.08) ; C8.2 v1(27.58,42.77) ; C19.2 v1(32.03,35.06) ; C1.2 v1(11.71,53.25) ; U6.2 v1(10.21,41.44) ; C44.2 v1(15.19,14.22) ; C26.2 v1(19.33,30.03) ; R16.2 v1(32.9,45.45) ; C42.2 v1(45.22,16.14) ; C4.2 v1(5.28,49.63) ; D3.C v2(36.26,11.91) ; v1(32.9,36.96) 32.75,37.11 R51.2 ; U11.2 v1(9.03,34.12) ; C25.2 v1(9.98,28.92) ; D8.A v1(20.63,13.48)
  TOP w0.635: C27.2 v2(28.67,31.23) ; D7.A 53.67,32.37 53.39,32.09 v2(53.39,31.46) C148.2 ; C141.2 74.61,18.93 v2(73.95,18.27) ; C137.2 v1(75.24,14.38) ; C24.2 v2(51.72,26.6) ; R44.2 v1(100.84,40.55) ; C49.2 v1(31.97,6.9) ; C22.2 C21.2 v2(39.12,28.31) ; C28.2 v1(100.04,21.87) ; C31.2 v1(24.24,23.7) C30.2 ; R74.2 v1(101.89,18.68) ; C133.2 v2(76.11,44) ; U15.2 v2(46.04,29.23) ; C142.2 v2(76.63,40.43) ; C129.2 C131.2 C43.2 v2(57.35,39.88) C147.2 v2(57.35,42.86) ; C47.2 v2(36.26,11.91) ; C29.2 v1(26.46,25.64)
  L2_GND w0.254: 86.32,1.55 J5.12 ; J5.12 87.11,3.37 ; J5.12 85.53,1.79 ; J5.12 85.29,2.58 ; J5.12 87.11,1.79 ; J5.12 85.53,3.37 ; J5.12 87.35,2.58 ; J5.12 86.32,3.61 ; J16.2 14.6,9.88 ; J16.2 13.69,7.96 ; J16.2 12.77,9.88 ; J16.2 12.77,11.8 ; J16.2 14.6,7.96 ; J16.2 14.6,11.8 ; J16.2 12.77,7.96 ; J16.2 13.69,11.8 ; J6.12 78.7,56.95 ; J6.12 77.91,55.13 ; J6.12 79.73,55.92 ; J6.12 78.7,54.89 ; J6.12 77.67,55.92 ; J6.12 77.91,56.71 ; J6.12 79.49,55.13 ; J6.12 79.49,56.71 ; 40.6,4.09 J3.11 ; J3.11 40.6,6.15 ; J3.11 39.81,4.33 ; J3.11 39.57,5.12 ; J3.11 39.81,5.91 ; J3.11 41.63,5.12 ; J3.11 41.39,5.91 ; J3.11 41.39,4.33 ; 6.24,15.63 TP32.1 ; TP32.1 6.45,14.89 ; TP32.1 7.19,16.58 ; TP32.1 8.14,15.63 ; TP32.1 7.93,16.37 ; TP32.1 7.19,14.68 ; TP32.1 7.93,14.89 ; TP32.1 6.45,16.37 ; TP17.1 22.77,29.32 ; TP17.1 22.03,27.63 ; TP17.1 21.29,27.85 ; TP17.1 21.29,29.32 ; TP17.1 21.08,28.59 ; TP17.1 22.98,28.59 ; TP17.1 22.03,29.54 ; TP17.1 22.77,27.85 ; 100.98,43.31 R13.3 ; R13.3 102.54,41.74 ; R13.3 100.98,41.74 ; R13.3 102.54,43.31 ; R13.3 101.76,43.54 ; R13.3 102.78,42.52 ; R13.3 101.76,41.51 ; R13.3 100.74,42.52 ; J16.SH2 23.6,2.58 ; J16.SH2 21.77,4.64 ; J16.SH2 23.6,4.64 ; J16.SH2 22.69,4.64 ; J16.SH2 21.77,2.58 ; 1.81,28.19 J11.4 ; J11.4 3.6,27.41 ; J11.4 3.84,28.19 ; J11.4 2.04,28.98 ; J11.4 2.82,29.21 ; J11.4 2.82,27.18 ; J11.4 3.6,28.98 ; J11.4 2.04,27.41 ; J14.3 53.7,41.1 ; J14.3 53.7,40.02 ; J14.3 53.83,40.56 ; J14.3 52.62,41.1 ; J14.3 52.62,40.02 ; 2.04,14.83 J13.4 ; J13.4 2.04,16.4 ; J13.4 3.84,15.62 ; J13.4 2.82,14.6 ; J13.4 3.6,14.83 ; J13.4 3.6,16.4 ; J13.4 1.81,15.62 ; J13.4 2.82,16.63 ; 26.38,52.35 J2.13 ; J2.13 26.38,54.41 ; J2.13 25.35,53.38 ; J2.13 25.59,54.17 ; J2.13 25.59,52.59 ; J2.13 27.41,53.38 ; J2.13 27.17,52.59 ; J2.13 27.17,54.17 ; 98.33,55.73 TP1.1 ; TP1.1 100.02,56.47 ; TP1.1 100.02,54.99 ; TP1.1 98.55,54.99 ; TP1.1 98.55,56.47 ; TP1.1 99.29,54.78 ; TP1.1 99.29,56.68 ; TP1.1 100.24,55.73 ; J16.3 19.8,11.8 ; J16.3 17.97,9.88 ; J16.3 17.97,7.96 ; J16.3 18.89,7.96 ; J16.3 18.89,11.8 ; J16.3 17.97,11.8 ; J16.3 19.8,9.88 ; J16.3 19.8,7.96 ; J12.3 17.85,28.83 ; J12.3 17.85,29.9 ; J12.3 16.78,29.9 ; J12.3 16.78,28.83 ; J12.3 17.99,29.36 ; J12.5 17.85,31.17 ; J12.5 16.78,30.1 ; J12.5 17.85,30.1 ; J12.5 17.99,30.63 ; J12.5 16.78,31.17 ; J16.SH1 13.7,4.64 ; J16.SH1 11.87,2.58 ; J16.SH1 13.7,2.58 ; J16.SH1 12.79,4.64 ; 52.62,41.29 J14.5 ; J14.5 53.7,42.37 ; J14.5 53.7,41.29 ; J14.5 53.83,41.83 ; J14.5 52.62,42.37 ; 42.35,5.91 J3.13 ; J3.13 43.14,4.09 ; J3.13 43.93,5.91 ; J3.13 43.93,4.33 ; J3.13 44.17,5.12 ; J3.13 42.11,5.12 ; J3.13 42.35,4.33 ; J3.13 43.14,6.15
  L3_MIX w0.254: J13.4 3.6,14.83 ; J13.4 2.82,16.63 ; J13.4 2.82,14.6 ; J13.4 1.81,15.62 ; J13.4 2.04,14.83 ; J13.4 3.6,16.4 ; J13.4 2.04,16.4 ; J13.4 3.84,15.62 ; 2.04,28.98 J11.4 ; J11.4 3.6,27.41 ; J11.4 2.82,27.18 ; J11.4 3.84,28.19 ; J11.4 2.04,27.41 ; J11.4 1.81,28.19 ; J11.4 2.82,29.21 ; J11.4 3.6,28.98 ; 21.77,2.58 J16.SH2 ; J16.SH2 23.6,4.64 ; J16.SH2 22.69,4.64 ; J16.SH2 23.6,2.58 ; J16.SH2 21.77,4.64 ; 39.81,4.33 J3.11 ; J3.11 41.39,4.33 ; J3.11 41.39,5.91 ; J3.11 41.63,5.12 ; 52.62,40.02 J14.3 52.62,41.1 ; J2.13 27.17,54.17 ; J2.13 26.38,52.35 ; J2.13 26.38,54.41 ; J2.13 27.41,53.38 ; J2.13 27.17,52.59 ; J2.13 25.35,53.38 ; J2.13 25.59,54.17 ; J2.13 25.59,52.59 ; J5.12 87.11,1.79 ; J5.12 85.53,3.37 ; J5.12 85.29,2.58 ; J5.12 87.11,3.37 ; J5.12 87.35,2.58 ; J5.12 86.32,3.61 ; J5.12 86.32,1.55 ; J5.12 85.53,1.79 ; J16.3 19.8,11.8 ; J16.3 19.8,7.96 ; J16.3 17.97,11.8 ; J16.3 18.89,7.96 ; J16.3 17.97,9.88 ; J16.3 17.97,7.96 ; J16.3 18.89,11.8 ; J16.3 19.8,9.88 ; R13.3 101.76,43.54 ; R13.3 102.54,43.31 ; R13.3 100.98,43.31 ; R13.3 100.74,42.52 ; R13.3 102.54,41.74 ; R13.3 101.76,41.51 ; R13.3 100.98,41.74 ; R13.3 102.78,42.52 ; J6.12 79.73,55.92 ; J6.12 79.49,56.71 ; J6.12 77.91,55.13 ; J6.12 79.49,55.13 ; J6.12 77.67,55.92 ; J6.12 77.91,56.71 ; J6.12 78.7,54.89 ; J16.SH1 12.79,4.64 ; J16.SH1 13.7,2.58 ; J16.SH1 11.87,2.58 ; J16.SH1 13.7,4.64 ; 42.11,5.12 J3.13 ; J3.13 43.93,5.91 ; J3.13 43.14,6.15 ; J3.13 43.93,4.33 ; J3.13 42.35,5.91 ; J3.13 44.17,5.12 ; J3.13 42.35,4.33 ; 98.55,54.99 TP1.1 ; TP1.1 99.29,54.78 ; TP1.1 99.29,56.68 ; TP1.1 98.55,56.47 ; TP1.1 100.02,54.99 ; TP1.1 100.24,55.73 ; TP1.1 100.02,56.47 ; TP1.1 98.33,55.73 ; TP17.1 22.77,29.32 ; TP17.1 22.77,27.85 ; TP17.1 21.29,27.85 ; TP17.1 22.03,29.54 ; TP17.1 21.29,29.32 ; TP17.1 22.98,28.59 ; TP17.1 22.03,27.63 ; TP17.1 21.08,28.59 ; 6.45,14.89 TP32.1 ; TP32.1 7.93,14.89 ; TP32.1 7.19,16.58 ; TP32.1 6.24,15.63 ; TP32.1 7.19,14.68 ; TP32.1 6.45,16.37 ; TP32.1 7.93,16.37 ; TP32.1 8.14,15.63 ; 12.77,7.96 J16.2 ; J16.2 14.6,7.96 ; J16.2 12.77,9.88 ; J16.2 13.69,7.96 ; J16.2 14.6,11.8 ; J16.2 14.6,9.88 ; J16.2 13.69,11.8 ; J16.2 12.77,11.8 ; J12.5 17.85,31.17 ; J12.5 16.78,30.1 ; J12.5 17.85,30.1 ; J12.5 16.78,31.17 ; J12.5 17.99,30.63 ; J12.3 17.85,28.83 ; J12.3 17.85,29.9 ; J12.3 16.78,28.83 ; J12.3 17.99,29.36 ; J12.3 16.78,29.9 ; 52.62,42.37 J14.5 52.62,41.29
  BOTTOM w0.254: 17.85,29.9 J12.3 17.99,29.36 ; J11.4 3.6,28.98 ; J11.4 3.84,28.19 ; J11.4 2.82,27.18 ; J11.4 2.82,29.21 ; J11.4 1.81,28.19 ; J11.4 3.6,27.41 ; J11.4 2.04,28.98 ; J11.4 2.04,27.41 ; J16.SH2 23.6,2.58 ; J16.SH2 21.77,4.64 ; J16.SH2 21.77,2.58 ; J16.SH2 22.69,4.64 ; J16.SH2 23.6,4.64 ; 2.04,14.83 J13.4 ; J13.4 3.84,15.62 ; J13.4 1.81,15.62 ; J13.4 2.04,16.4 ; J13.4 3.6,16.4 ; J13.4 2.82,14.6 ; J13.4 2.82,16.63 ; J13.4 3.6,14.83 ; J3.13 43.14,6.15 ; J3.13 43.93,5.91 ; J3.13 43.93,4.33 ; J3.13 43.14,4.09 ; J3.13 42.35,4.33 ; 77.91,56.71 J6.12 ; J6.12 78.7,54.89 ; J6.12 77.67,55.92 ; J6.12 79.49,55.13 ; J6.12 77.91,55.13 ; J6.12 78.7,56.95 ; J6.12 79.49,56.71 ; J2.13 27.17,54.17 ; J2.13 25.59,52.59 ; J2.13 27.17,52.59 ; J2.13 27.41,53.38 ; J2.13 26.38,52.35 ; J2.13 26.38,54.41 ; J2.13 25.59,54.17 ; J16.2 14.6,11.8 ; J16.2 12.77,9.88 ; J16.2 14.6,9.88 ; J16.2 13.69,11.8 ; 22.03,27.63 TP17.1 ; TP17.1 21.29,27.85 ; TP17.1 22.77,29.32 ; TP17.1 22.98,28.59 ; TP17.1 22.03,29.54 ; TP17.1 21.08,28.59 ; TP17.1 21.29,29.32 ; 6.45,14.89 TP32.1 ; TP32.1 8.14,15.63 ; TP32.1 6.45,16.37 ; TP32.1 7.19,16.58 ; TP32.1 7.19,14.68 ; TP32.1 7.93,16.37 ; TP32.1 7.93,14.89 ; TP32.1 6.24,15.63 ; J14.5 53.7,42.37 ; J14.5 53.7,41.29 ; J14.5 53.83,41.83 ; J3.11 40.6,6.15 ; J3.11 41.39,4.33 ; J3.11 40.6,4.09 ; J3.11 39.81,4.33 ; J3.11 41.39,5.91 ; 11.87,2.58 J16.SH1 ; J16.SH1 12.79,4.64 ; J16.SH1 13.7,2.58 ; J16.SH1 13.7,4.64 ; J12.5 17.85,31.17 ; J12.5 17.99,30.63 ; J12.5 17.85,30.1 ; 17.97,9.88 J16.3 ; J16.3 17.97,11.8 ; J16.3 18.89,11.8 ; J16.3 19.8,11.8 ; J16.3 19.8,9.88 ; 53.83,40.56 J14.3 53.7,41.1
  vias: v1(2.24,12.48) v1(11.15,57.04) v1(15.45,39.34) v1(18.05,39.02) v1(18.73,39.71) v1(18.83,38.21) v1(19.52,40.53) v1(19.53,38.91) v1(20.2,41.2) v1(20.33,39.71) v1(21.01,40.39) v1(21.39,35.64) v1(22.2,23.4) v1(24.6,32.44) v1(32.57,22.1) v1(32.52,19.9) v1(32.52,17.71) v1(34.73,22.15) v1(34.77,21.02) v1(34.76,19.89) v1(34.76,18.74) v1(34.75,17.68) v1(36.94,22.12) v1(36.93,19.88) v1(36.94,17.68) v1(45.19,13.73) v1(47.96,16.63) v1(49.24,4.81) v1(53.27,7.05) v1(56.9,43.96) v1(58.21,44.15) v1(58.73,27.94) v1(65.38,27.87) v1(86.4,27.04) v1(88.06,46.31) v2(63.97,35.2) v2(64.57,34.22) v4(0.78,49.62) v4(0.8,37.85) v4(0.8,35.7) v4(0.8,33.56) v4(0.8,31.41) v4(0.8,29.27) v4(0.8,27.12) v4(0.8,24.98) v4(0.8,22.83) v4(0.8,20.69) v4(0.8,18.54) v4(0.8,16.4) v4(0.8,14.25) v4(0.8,12.11) v4(0.81,9.96) v4(0.86,7.67) v4(1.6,5.45) v4(2.26,13.45) v4(2.67,3.82) v4(3.13,55.03) v4(3.15,48.73) v4(3.42,13.54) v4(3.46,7.32) v4(4.32,48.71) v4(4.37,2.23) v4(4.47,56.17) v4(5.71,47.41) v4(5.71,46.4) v4(6.06,24.62) v4(6.06,19.7) v4(6.06,18.19) v4(6.06,16.67) v4(6.41,57.22) v4(6.71,1.11) v4(6.88,49.66) v4(7.11,26.98) v4(7.24,19.68) v4(7.25,13.85) v4(7.31,23.19) v4(8.09,57.55) v4(8.08,27.97) v4(8.42,17.44) v4(8.41,13.14) v4(8.88,0.8) v4(9.18,22.76) v4(10.23,57.55) v4(10.6,15.41) v4(10.68,22.63) v4(11.07,0.96) v4(11.14,12.32) v4(11.8,22.49) v4(12.38,57.55) v4(12.38,5.22) v4(12.5,34.57) v4(12.58,12.8) v4(13.11,33.76) v4(13.19,16.54) v4(13.23,18.06) v4(13.45,5.22) v4(14.52,57.55) v4(14.52,5.22) v4(14.52,4.15) v4(14.52,3.08) v4(14.52,2) v4(14.52,0.93) v4(14.93,22.93) v4(15.04,31.01) v4(15.07,29.08) v4(15.19,18.13) v4(15.19,16.59) v4(15.6,11.66) v4(15.6,10.58) v4(15.57,9.48) v4(15.57,8.38) v4(15.6,5.22) v4(15.6,4.15) v4(15.6,3.08) v4(15.6,2) v4(15.6,0.93) v4(16.05,22.95) v4(16.67,57.55) v4(16.67,11.66) v4(16.67,10.58) v4(16.66,9.48) v4(16.66,8.38) v4(16.67,5.22) v4(16.67,4.15) v4(16.67,3.08) v4(16.67,2) v4(16.67,0.93) v4(16.94,18.11) v4(17.79,22.98) v4(17.74,11.66) v4(17.74,10.58) v4(17.83,36.14) v4(18.26,13.28) v4(18.46,16.57) v4(18.56,30.55) v4(18.51,29.62) v4(19.07,18.46) v4(19.25,35.32) v4(19.48,6.17) v4(19.53,51.65) v4(19.52,22.93) v4(20.07,57.27) v4(20.06,21.91) v4(20.06,19.08) v4(20.14,54.63) v4(20.31,16.49) v4(20.56,30.9) v4(20.76,50.37) v4(20.96,11.66) v4(20.96,10.58) v4(20.96,5.22) v4(20.97,4.15) v4(20.97,3.08) v4(20.97,2) v4(20.97,0.93) v4(21.35,21.89) v4(21.6,17.67) v4(21.63,30.9) v4(21.72,51.68) v4(22.03,5.22) v4(22.58,54.62) v4(22.55,50.79) v4(22.57,21.47) v4(22.6,57.32) v4(22.67,19.48) v4(22.7,30.9) v4(22.71,26.37) v4(23.11,5.22) v4(23.43,16.76) v4(23.51,14.29) v4(23.77,30.9) v4(23.8,19.56) v4(24.18,5.22) v4(24.19,4.15) v4(24.19,3.08) v4(24.19,2) v4(24.19,0.93) v4(24.49,46.06) v4(24.76,42.34) v4(24.85,30.9) v4(24.94,19.56) v4(25.04,57.3) v4(25.65,3.23) v4(25.78,43.34) v4(26.09,34.11) v4(26.34,42.3) v4(26.44,32.08) v4(26.48,22.91) v4(26.59,33.12) v4(26.52,19.55) v4(26.9,28.01) v4(27.1,51.95) v4(27.33,34.1) v4(27.4,32.97) v4(27.44,21.53) v4(27.65,57.25) v4(28.72,26.03) v4(29.23,1.56) v4(30.09,57.23) v4(30,27.62) v4(30.65,48.09) v4(31.82,1.51) v4(32.68,57.25) v4(33.46,46.3) v4(33.69,25.21) v4(34.19,1.45) v4(34.33,45.38) v4(35.16,57.21) v4(36.33,37.13) v4(36.89,45.66) v4(36.82,1.42) v4(37.15,51.94) v4(37.38,24.13) v4(37.34,15.49) v4(37.69,37.83) v4(37.8,57.23) v4(38.31,51.93) v4(38.42,45.65) v4(39.26,1.42) v4(40,51.95) v4(40.43,57.06) v4(40.97,22.83) v4(41.02,24.62) v4(42.8,57.06) v4(42.71,39.26) v4(42.95,51.95) v4(43.59,40.07) v4(44.47,51.94) v4(44.69,54.51) v4(45.06,11.16) v4(45.04,10.25) v4(46.36,51.94) v4(46.61,6.34) v4(46.94,56.85) v4(47.45,15.51) v4(48.2,4.28) v4(48.62,23.72) v4(49.45,54.58) v4(49.55,51.94) v4(49.73,6.91) v4(49.83,17.25) v4(50.73,44.06) v4(51.66,51.94) v4(52.02,56.7) v4(53.47,25.44) v4(53.44,10.58) v4(53.99,51.94) v4(54.58,56.66) v4(54.51,30.3) v4(54.93,8.89) v4(55.14,25.44) v4(55.64,18.53) v4(56.3,52.02) v4(56.55,19.38) v4(56.81,25.43) v4(57.2,56.73) v4(57.26,24.06) v4(58.04,52.06) v4(58.61,19.4) v4(59.52,20.21) v4(59.72,56.7) v4(59.89,22.47) v4(60.66,6.68) v4(61.9,6.49) v4(62.21,56.73) v4(63.16,6.48) v4(65.39,6.27) v4(65.64,8.95) v4(66.59,6.33) v4(67.43,17.39) v4(67.84,7.29) v4(68.69,20.39) v4(69.11,6.62) v4(69.79,52.38) v4(70.92,5.08) v4(72.75,14.2) v4(72.79,13.24) v4(73.16,45.94) v4(73.74,9.32) v4(74.56,35.16) v4(74.95,56.76) v4(76.04,22.82) v4(76.66,35.24) v4(76.74,49.8) v4(77.4,54.52) v4(78.05,49.8) v4(78.15,18.15) v4(78.23,13.9) v4(79.78,35.22) v4(80.06,19.02) v4(80.25,33.99) v4(80.5,18.33) v4(80.61,48.1) v4(80.71,9.32) v4(80.89,50.23) v4(81.38,45.04) v4(81.7,9.33) v4(82.3,48.01) v4(82.51,4.41) v4(82.68,46.52) v4(82.9,45.07) v4(83.25,9.63) v4(83.9,48.28) v4(84.18,21.81) v4(84.43,50.19) v4(84.6,36.27) v4(84.51,35.35) v4(84.64,45.07) v4(85.03,4.49) v4(85.16,9.71) v4(85.93,48.91) v4(86.07,16.05) v4(86.18,48.04) v4(86.41,45.13) v4(86.7,46.58) v4(87.78,45.23) v4(87.92,9.73) v4(88.97,12.07) v4(90.14,40.31) v4(90.4,45.81) v4(90.56,22.15) v4(90.88,36.12) v4(90.98,33) v4(91.17,32.18) v4(91.28,44.03) v4(91.2,9.88) v4(91.45,41.73) v4(91.56,10.83) v4(91.94,38.67) v4(91.92,24.82) v4(92.1,20.02) v4(92.08,6.52) v4(92.25,45.93) v4(92.25,27.9) v4(92.47,36.72) v4(92.43,8.09) v4(92.59,44.05) v4(92.92,18.57) v4(93.07,38.08) v4(93.48,45.4) v4(93.51,11.01) v4(94.07,36.72) v4(94.1,17.94) v4(94.66,38.45) v4(96.11,20.16) v4(96.11,17.19) v4(97.62,21.62) v4(97.61,16.2) v4(98.23,44.36) v4(98.5,41.95) v4(98.63,21.64) v4(98.76,39.84) v4(98.89,42.76) v4(98.9,43.74) v4(99.27,26.64) v4(99.25,16.23) v4(99.45,18.27) v4(99.5,0.96) v4(99.62,34.63) v4(99.95,57.25) v4(100.02,37.8) v4(100.04,22.96) v4(100.67,43.99) v4(100.71,46.09) v4(101,1.56) v4(101.43,15.67) v4(101.58,56.65) v4(102.04,40.35) v4(103.06,55.58) v4(104.35,54.26) v4(105.18,5.74) v4(105.4,18.48) v4(105.35,16.48) v4(105.6,51.91) v4(105.89,49.79) v4(105.89,47.65) v4(105.89,45.5) v4(105.89,43.36) v4(105.89,41.21) v4(105.89,39.07) v4(105.89,34.77) v4(105.89,30.48) v4(105.89,28.34) v4(105.89,24.05) v4(105.89,21.9) v4(105.89,17.61) v4(105.89,15.47) v4(105.83,7.7)
